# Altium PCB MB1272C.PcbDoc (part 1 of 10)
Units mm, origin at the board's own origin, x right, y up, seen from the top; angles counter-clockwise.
Board outline 101 x 71 mm, 6 copper layers (Top Layer, Signal Layer 1, Signal Layer 2, Signal Layer 3, Signal Layer 4, Bottom Layer), stack 1.552 mm thick; 520 components, 478 nets, 2156 pads, 1894 vias.
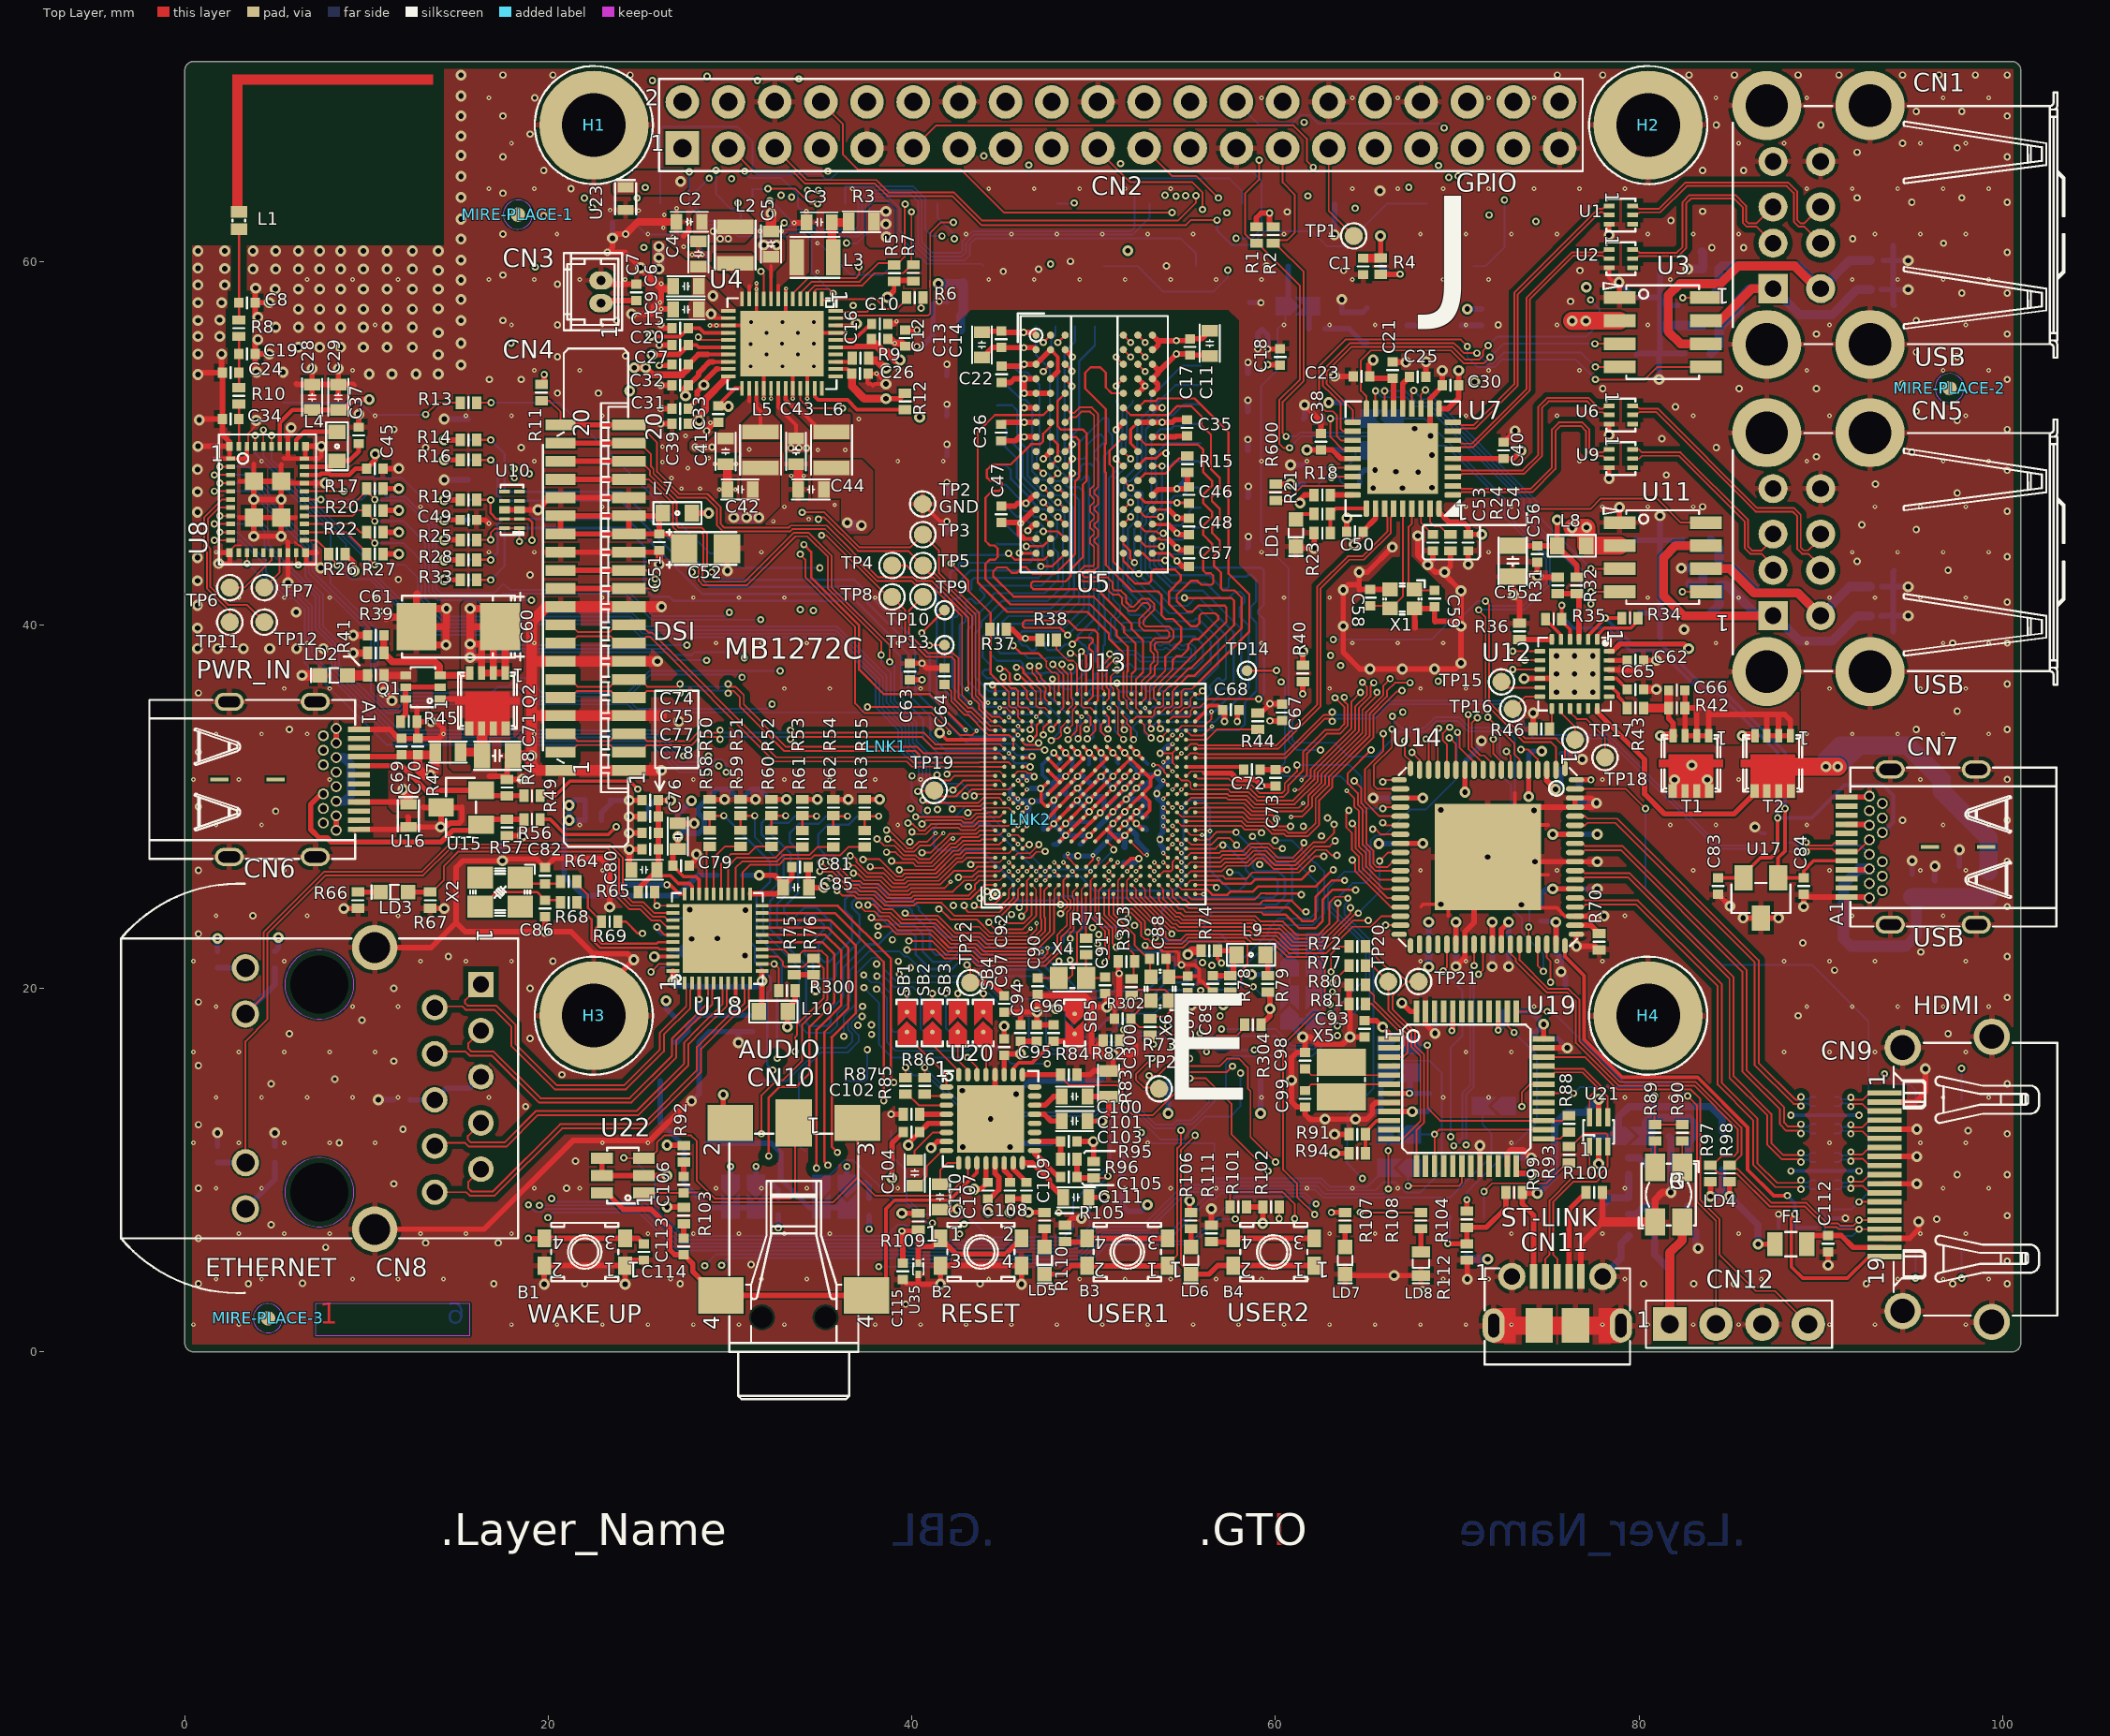
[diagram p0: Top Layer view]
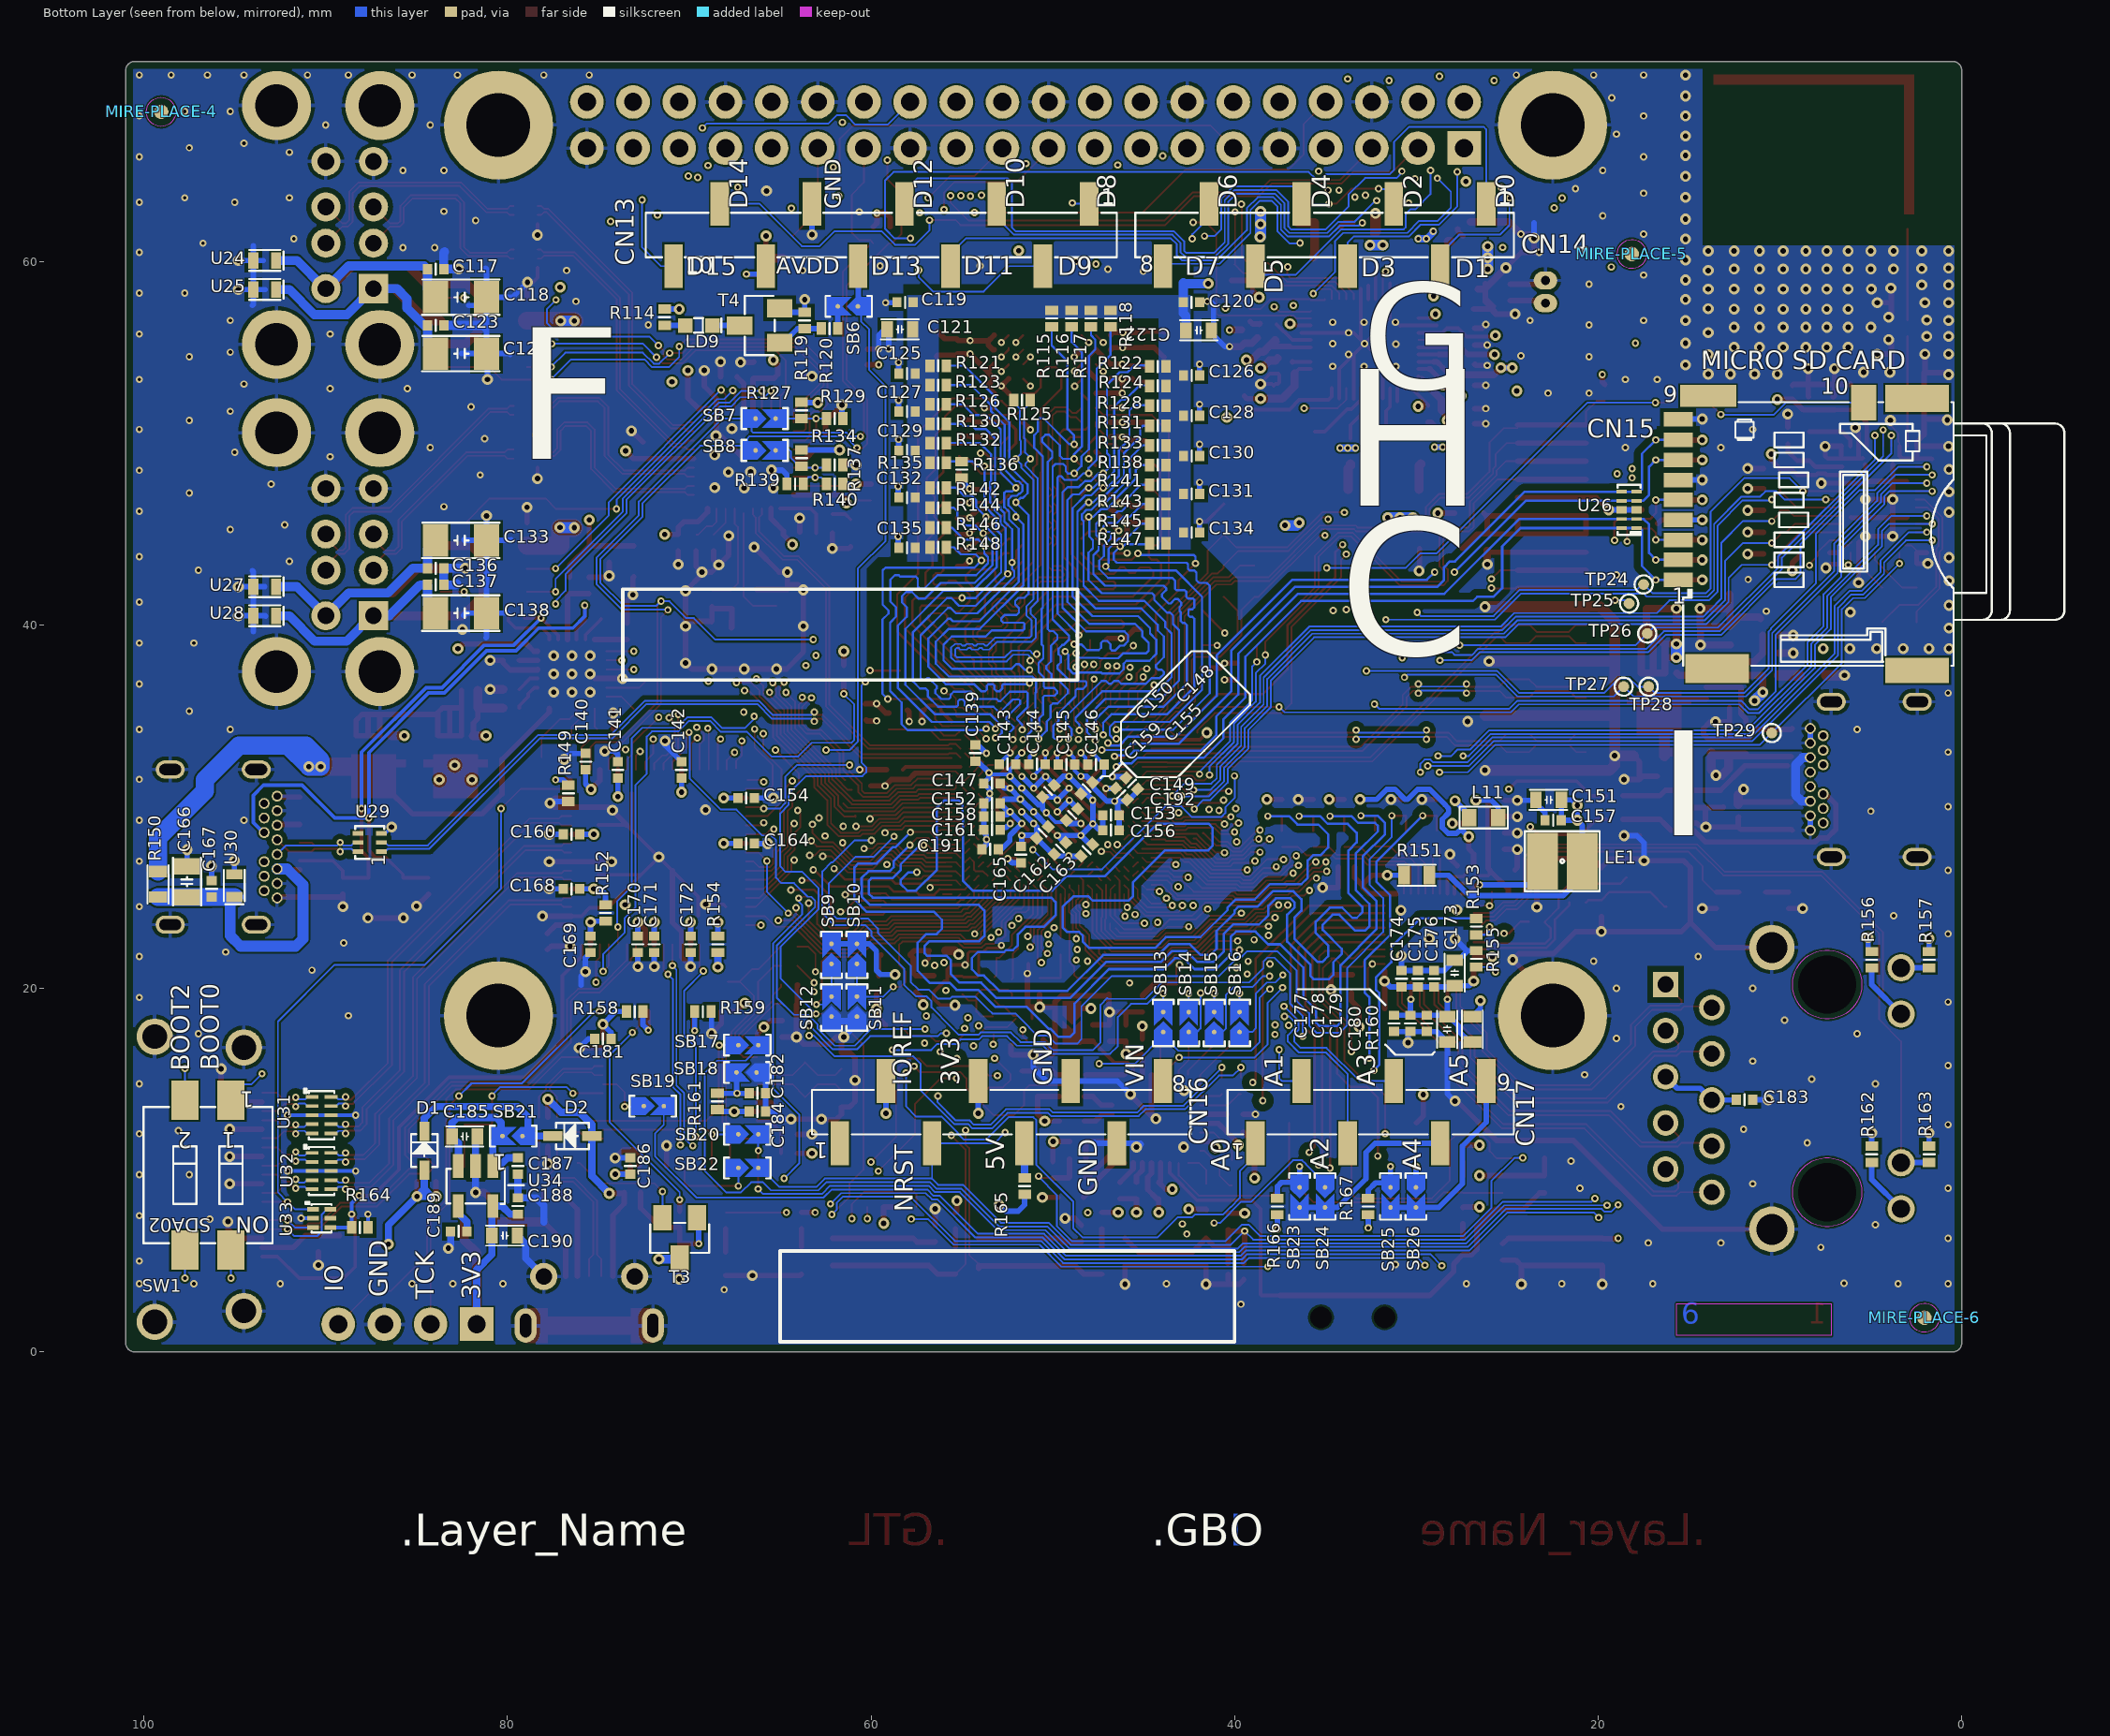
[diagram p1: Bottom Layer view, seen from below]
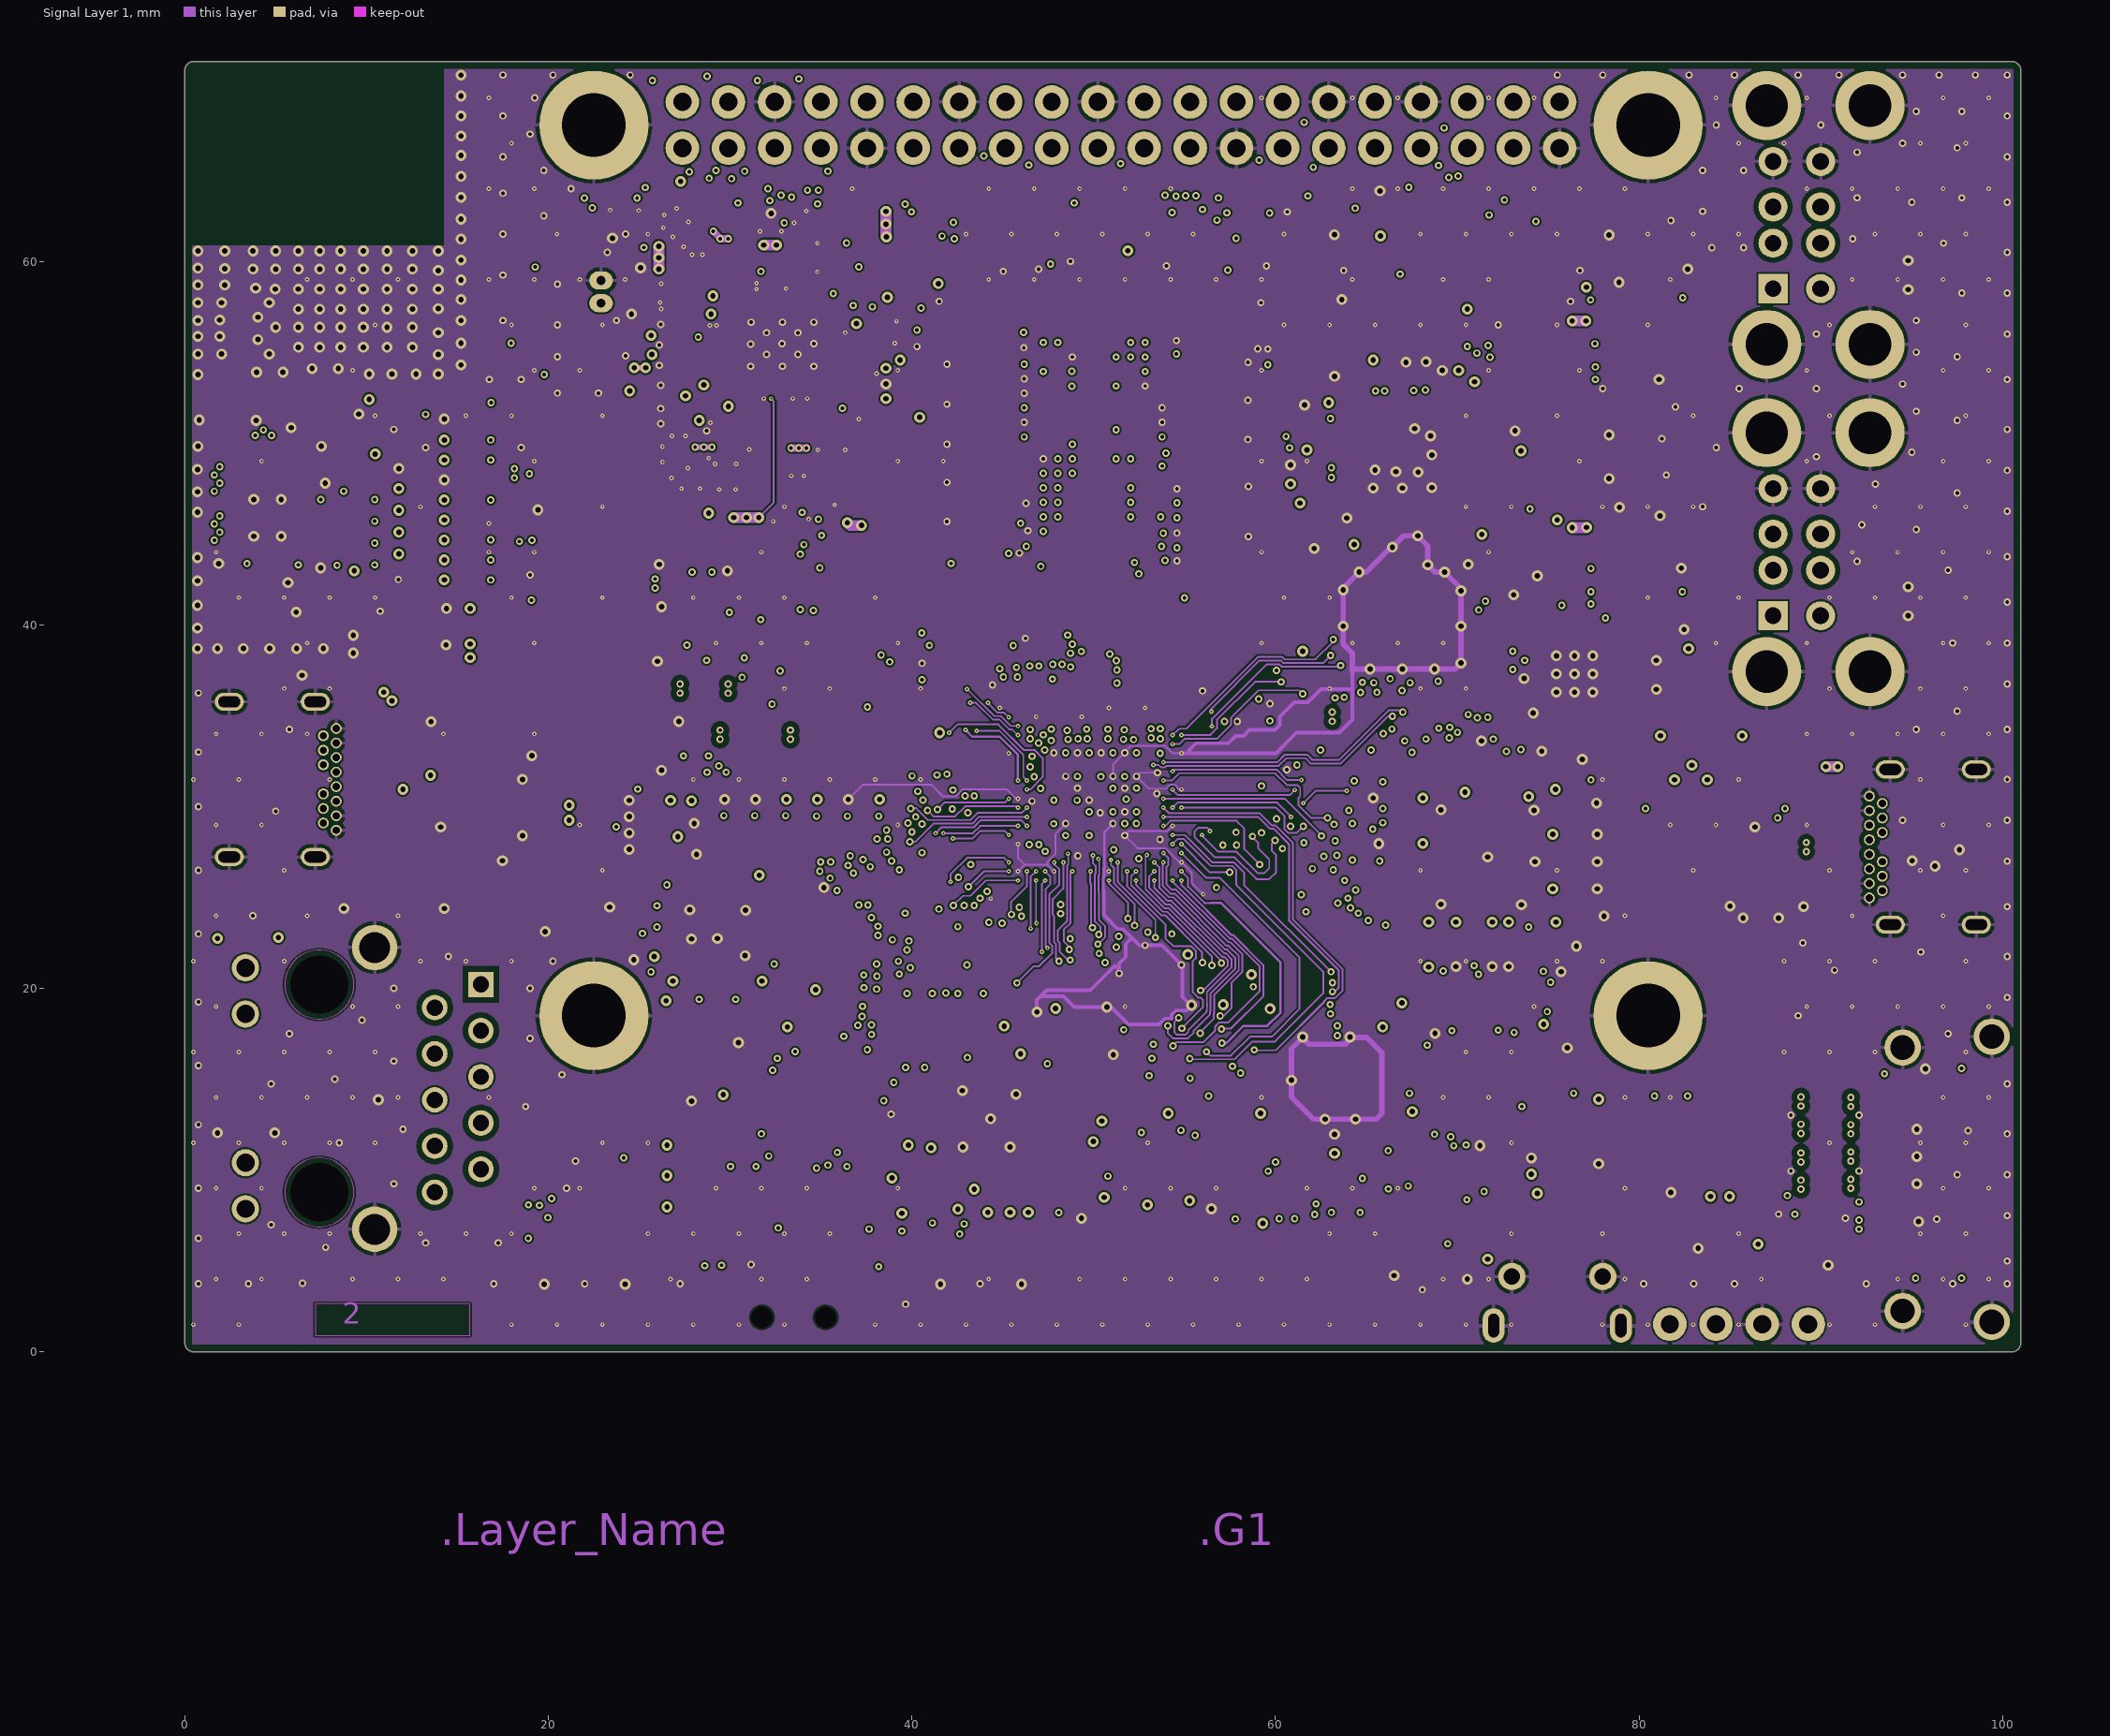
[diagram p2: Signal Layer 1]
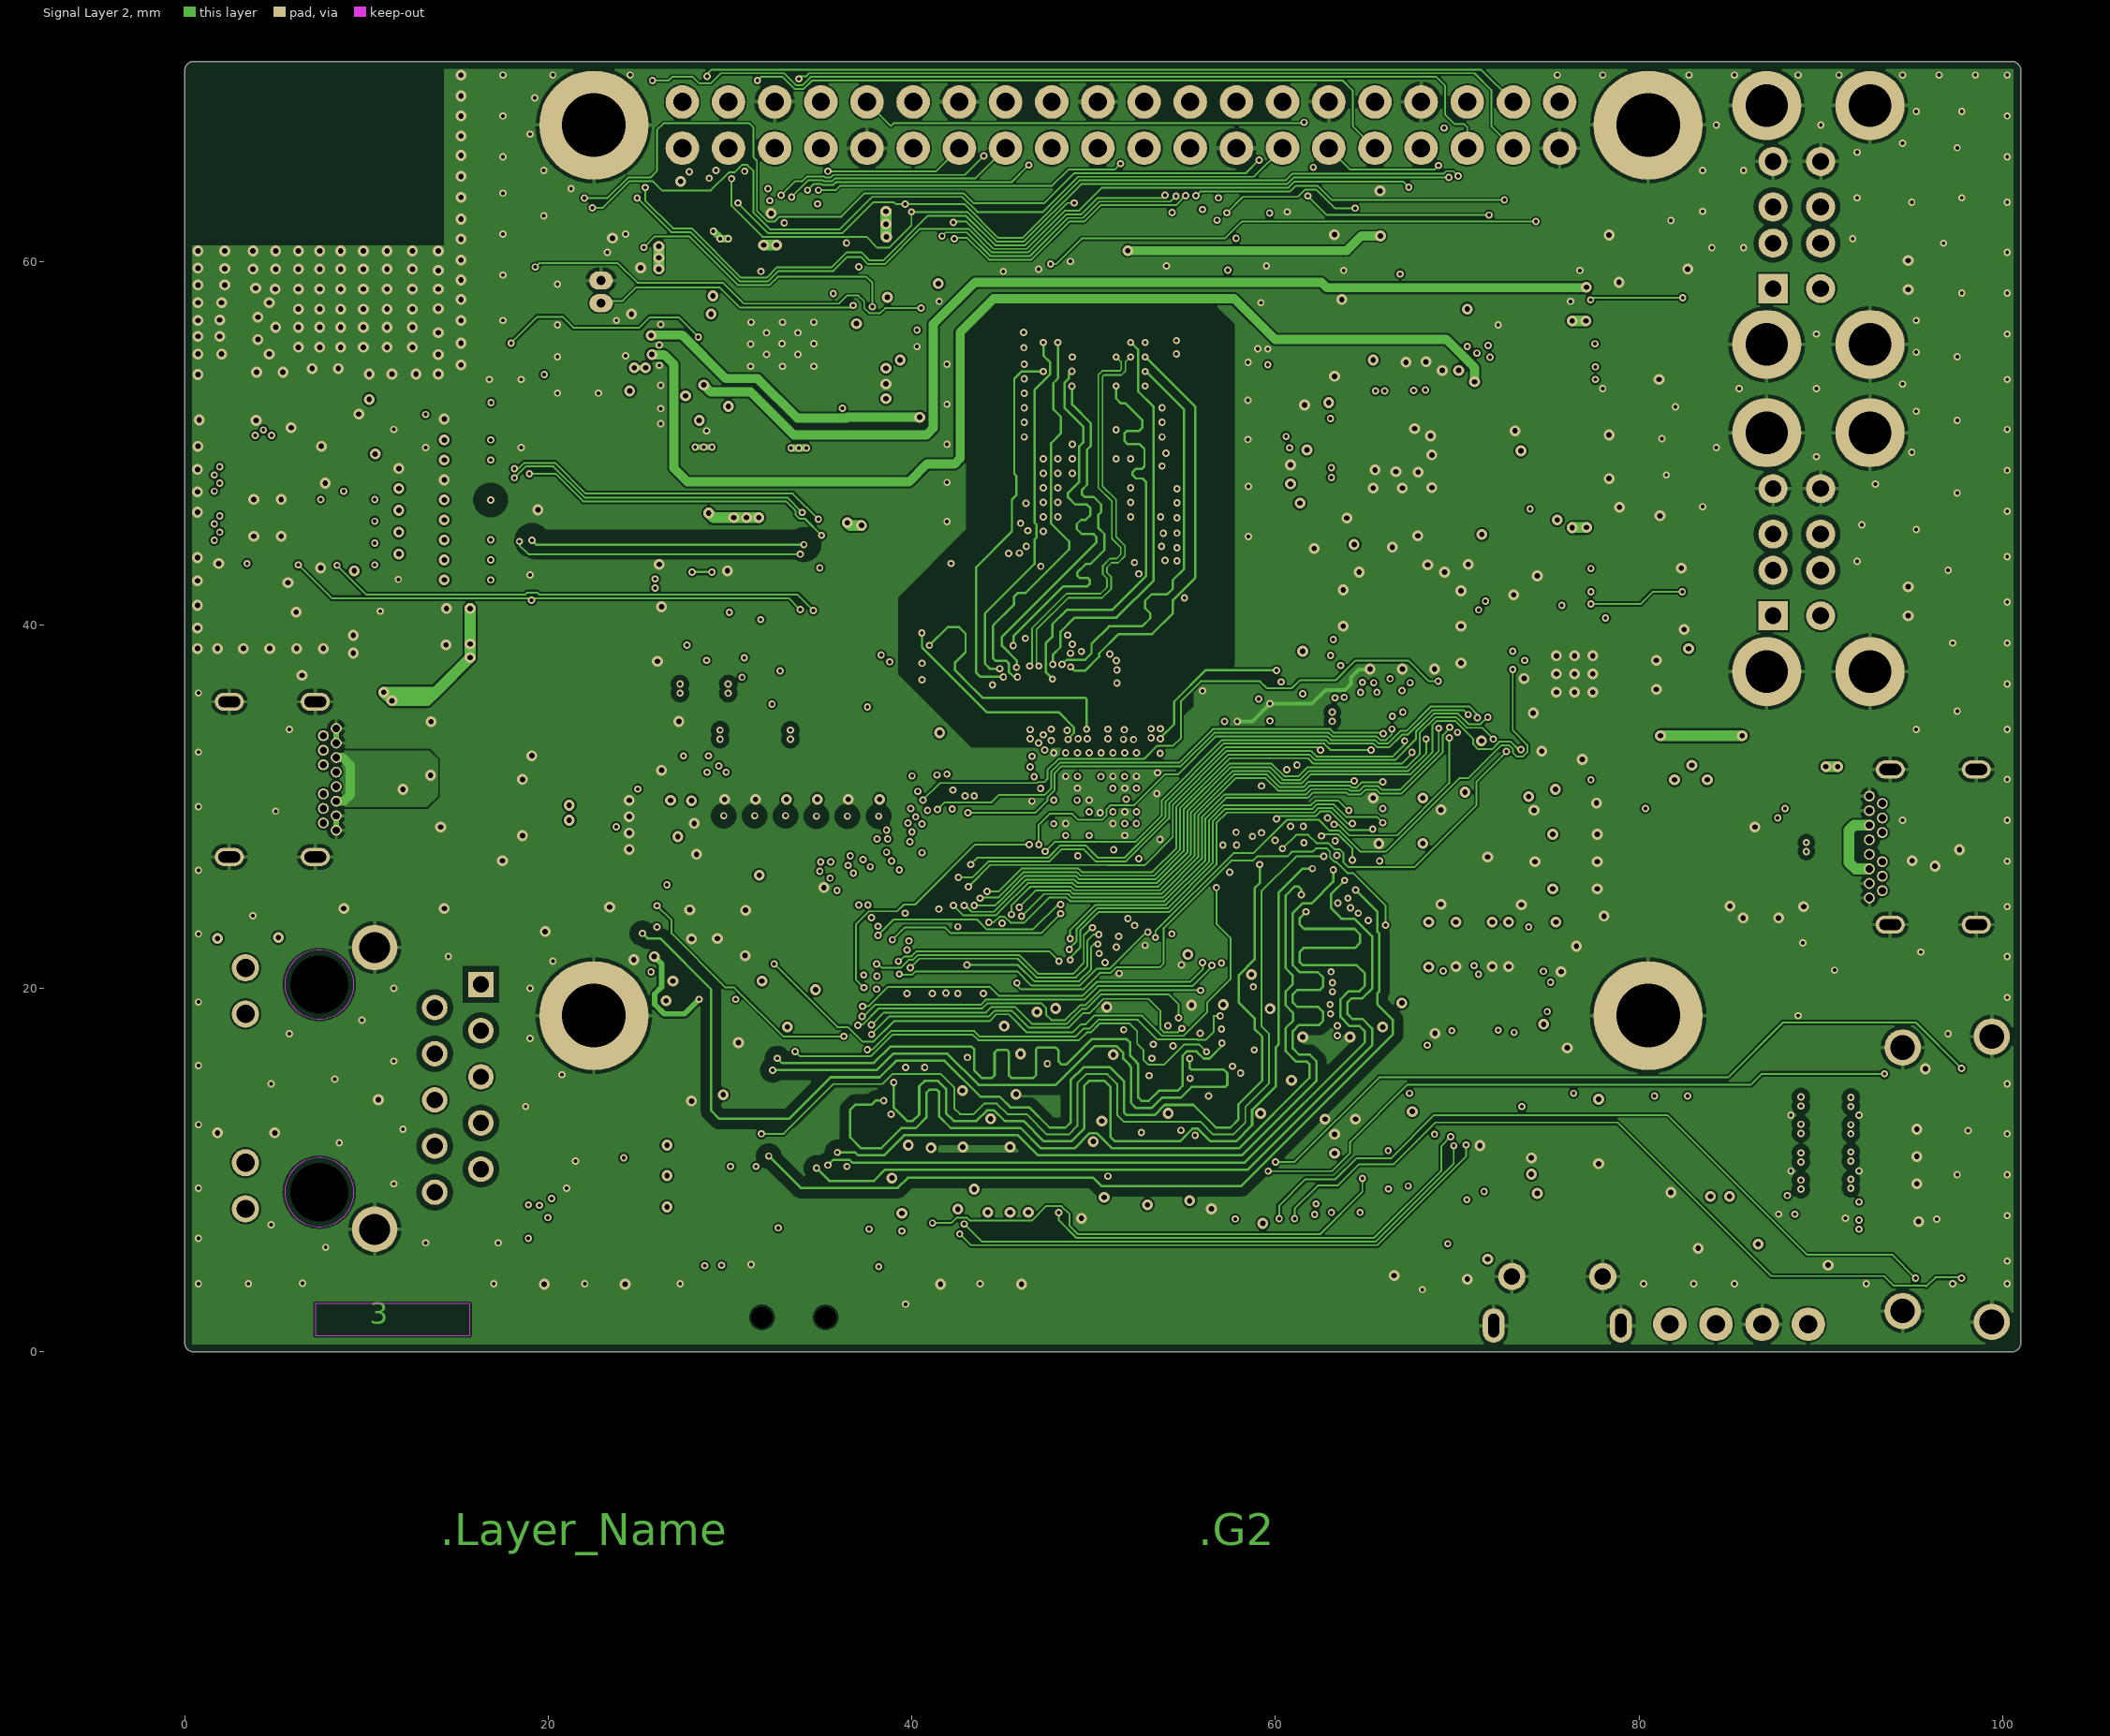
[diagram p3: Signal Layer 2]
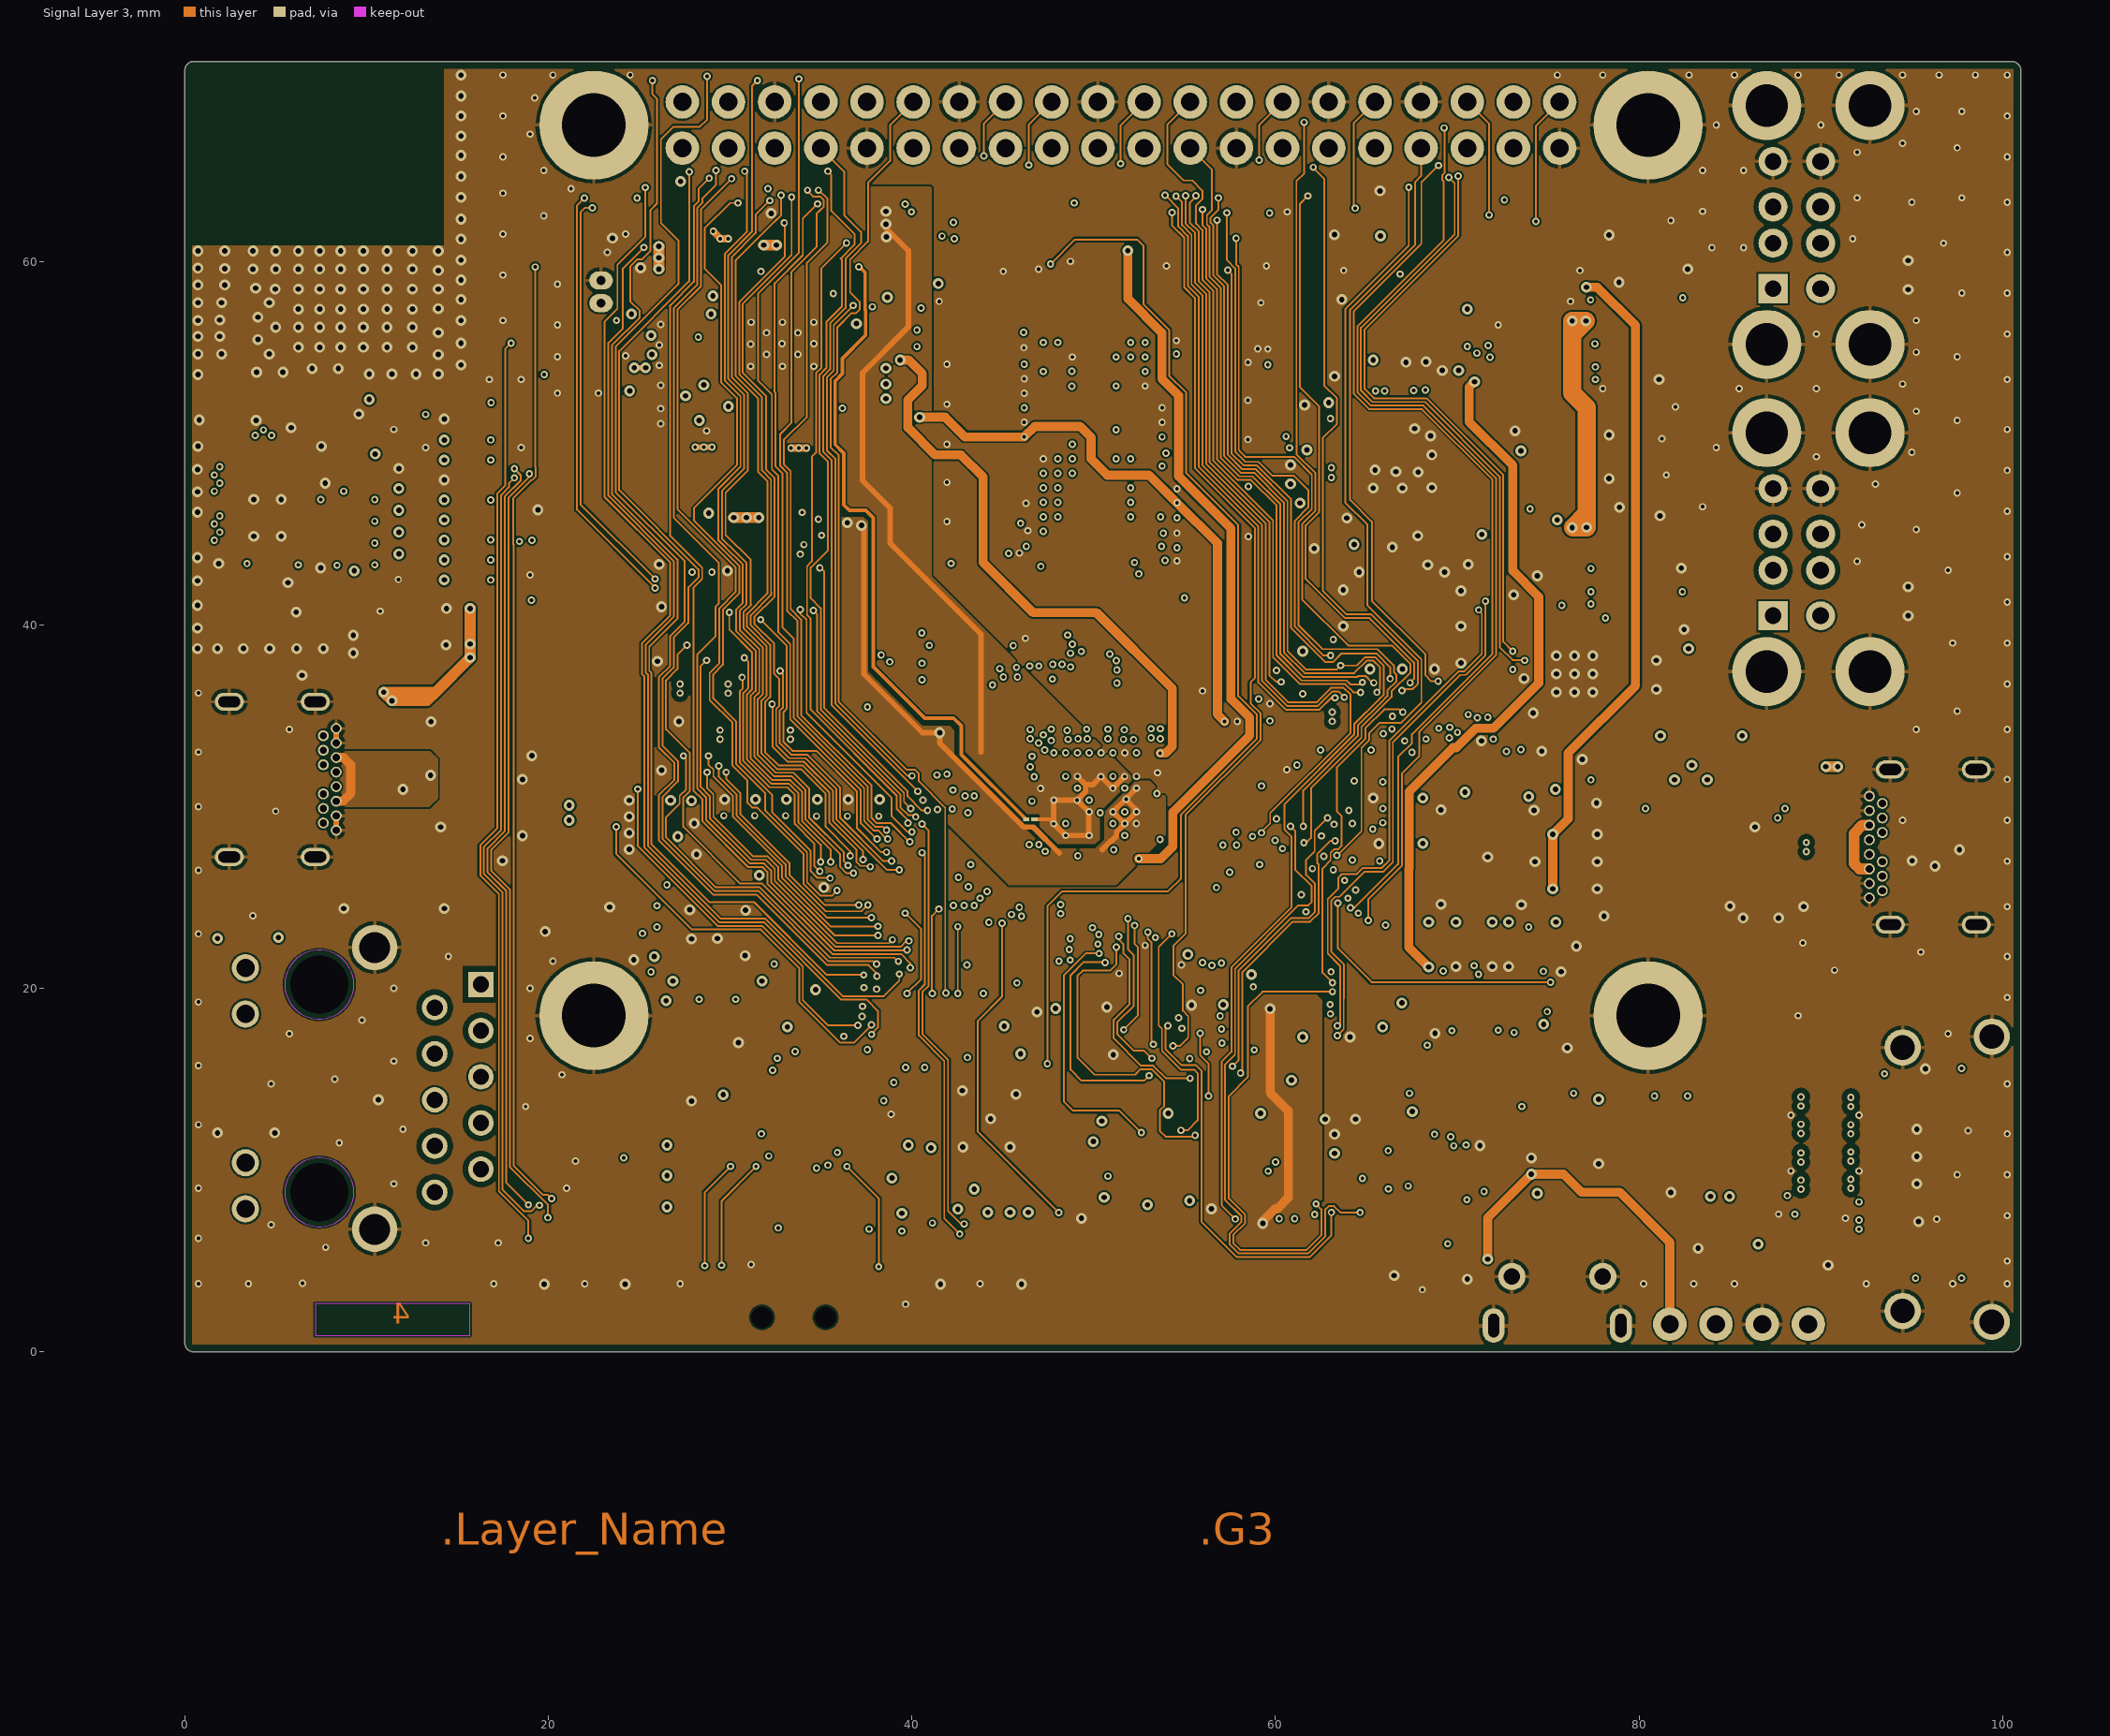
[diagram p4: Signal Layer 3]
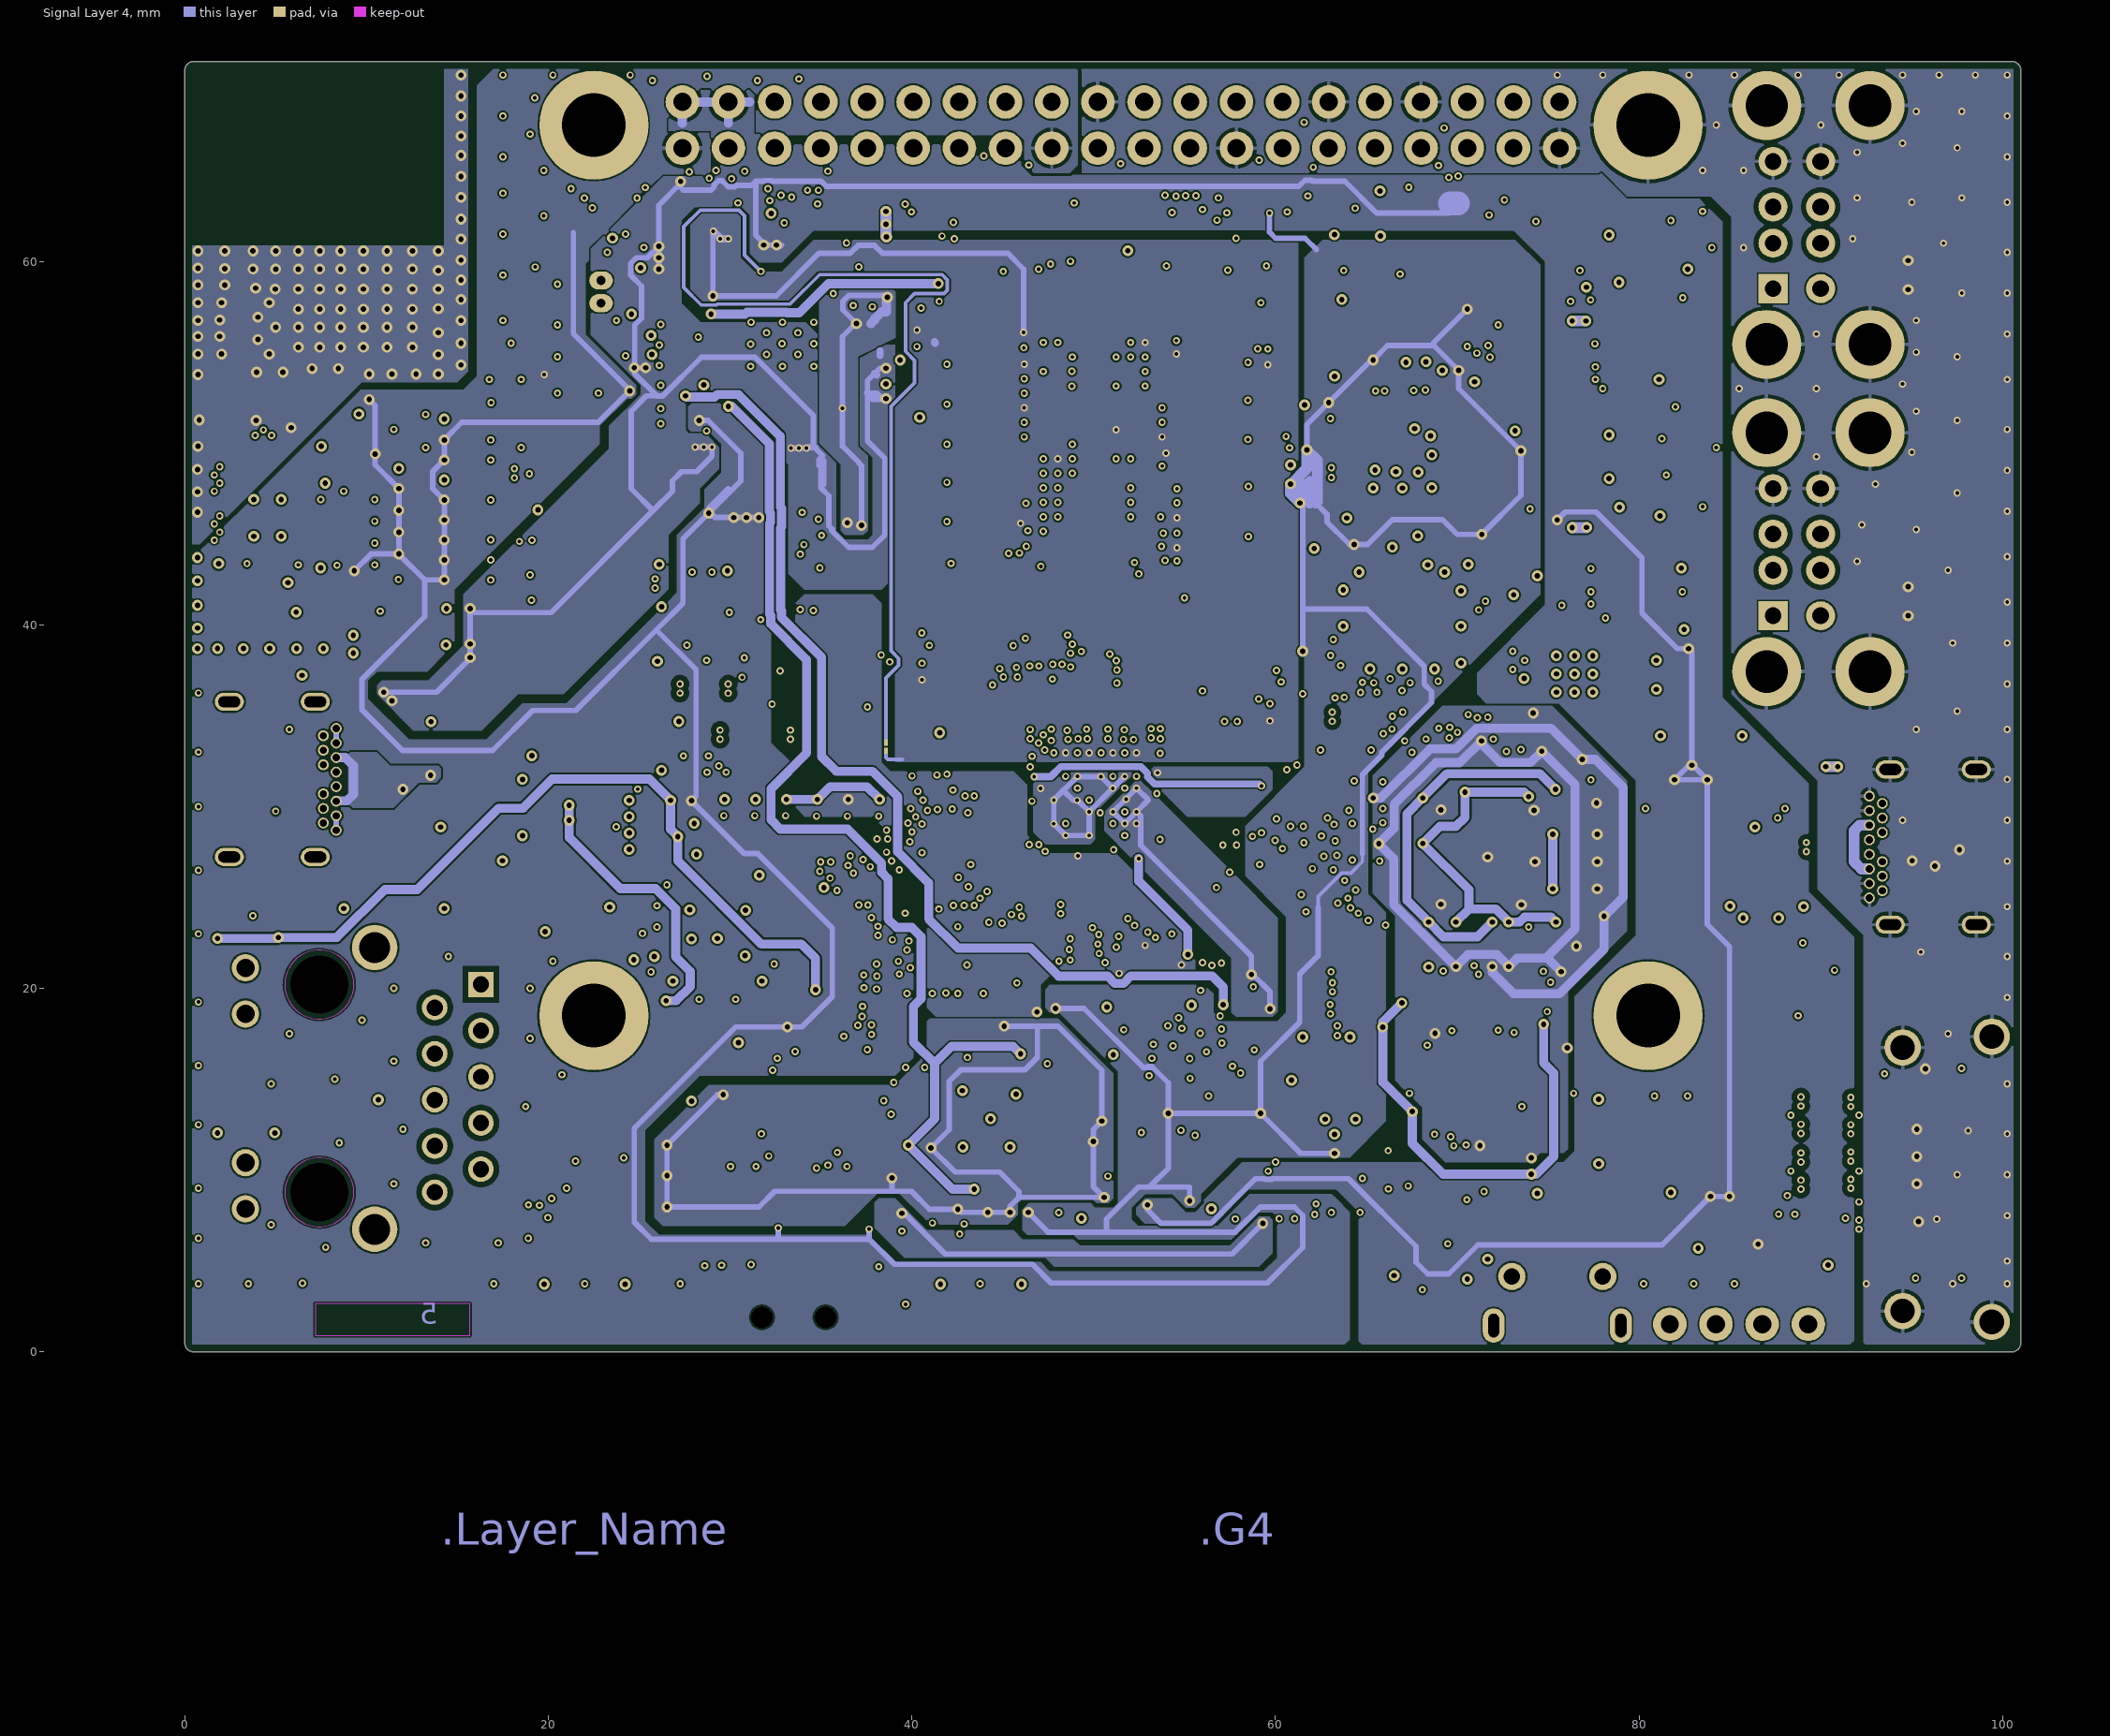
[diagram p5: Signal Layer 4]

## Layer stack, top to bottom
Top Solder: solder mask 0.0203, Solder Resist, Dk 3.5
Top Layer: signal copper 0.035
Dielectric 1: prepreg 0.0986, IT-180A 3313H, Dk 4.2
Signal Layer 1: signal copper 0.035
Dielectric 2: core 0.13, IT-180A, Dk 4.2
Signal Layer 2: signal copper 0.035
Dielectric 3: core 0.885, IT-180A 1080*2, Dk 4.25
Signal Layer 3: signal copper 0.035
Dielectric 4: core 0.13, IT-180A, Dk 4.2
Signal Layer 4: signal copper 0.035
Dielectric 5: prepreg 0.0986, IT-180A 3313H, Dk 4.2
Bottom Layer: signal copper 0.035
Bottom Solder: solder mask 0.0203, Solder Resist, Dk 3.5

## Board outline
0,0.5 ccw(c0.5,0.5) 0.5,0 100.5,0 ccw(c100.5,0.5) 101,0.5 101,70.5 ccw(c100.5,70.5) 100.5,71 0.5,71 ccw(c0.5,70.5) 0,70.5

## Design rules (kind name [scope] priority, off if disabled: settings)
BoardOutlineClearance [All] p1: gap=0.4 ignorepadtopadclearanceinfootprint=FALSE
Clearance Clearance_BGA05 [InComponentClass('CC_BGA05')] p1: gap=0.1 ignorepadtopadclearanceinfootprint=TRUE except(0.09: Arc-Track Track-SMDPad; 0.15: Arc-Fill Track-Fill SMDPad-Fill THPad-Fill Via-Fill Fill-Fill; 0.2: Arc-THPad Track-THPad SMDPad-SMDPad SMDPad-THPad THPad-THPad)
Clearance Clearance_BUS_50R_RGMII_ETH_L1 [InNetClass('NC_BUS_50R_RGMII_ETH-ALL') vs OnLayer('Top Layer')] p2: gap=0.1 ignorepadtopadclearanceinfootprint=TRUE except(0.15: Arc-Fill Track-Fill SMDPad-Fill THPad-Fill Via-Fill Fill-Fill; 0.2: Arc-THPad Track-THPad SMDPad-SMDPad SMDPad-THPad THPad-THPad; 0.26: Track-Track; 0.39: Arc-Poly Track-Poly SMDPad-Poly THPad-Poly Via-Poly Fill-Poly Poly-Poly)
Clearance Clearance_BUS_50R_RGMII_ETH_L6 [InNetClass('NC_BUS_50R_RGMII_ETH-ALL') vs OnLayer('Bottom Layer')] p3: gap=0.1 ignorepadtopadclearanceinfootprint=TRUE except(0.15: Arc-Fill Track-Fill SMDPad-Fill THPad-Fill Via-Fill Fill-Fill; 0.2: Arc-THPad Track-THPad SMDPad-SMDPad SMDPad-THPad THPad-THPad; 0.26: Track-Track; 0.39: Arc-Poly Track-Poly SMDPad-Poly THPad-Poly Via-Poly Fill-Poly Poly-Poly)
Clearance Clearance_BUS_50R_RGMII_ETH_L3 [InNetClass('NC_BUS_50R_RGMII_ETH-ALL') vs OnLayer('Signal Layer 2')] p4: gap=0.1 ignorepadtopadclearanceinfootprint=TRUE except(0.15: Arc-Fill Track-Fill SMDPad-Fill THPad-Fill Via-Fill Fill-Fill; 0.2: Arc-THPad Track-THPad SMDPad-SMDPad SMDPad-THPad THPad-THPad; 0.26: Track-Track; 0.5: Arc-Poly Track-Poly SMDPad-Poly THPad-Poly Via-Poly Fill-Poly Poly-Poly)
Clearance Clearance_DIFFPAIR_100R_DSI [InNetClass('NC_DIFFPAIR_100R_DSI')] p5: gap=0.1 ignorepadtopadclearanceinfootprint=TRUE except(0.15: Arc-Fill Track-Fill SMDPad-Fill THPad-Fill Via-Fill Fill-Fill; 0.2: Arc-THPad Track-THPad SMDPad-SMDPad SMDPad-THPad THPad-THPad; 0.3: Arc-Poly Track-Poly SMDPad-Poly THPad-Poly Via-Poly Fill-Poly Poly-Poly)
Clearance Clearance_DIFFPAIR_100R_RGMII-RJ45 [InNetClass('NC_DIFFPAIR_100R_RGMII-RJ45')] p6: gap=0.1 ignorepadtopadclearanceinfootprint=TRUE except(0.15: Arc-Fill Track-Fill SMDPad-Fill THPad-Fill Via-Fill Fill-Fill; 0.2: Arc-THPad Track-THPad SMDPad-SMDPad SMDPad-THPad THPad-THPad; 0.3: Arc-Poly Track-Poly SMDPad-Poly THPad-Poly Via-Poly Fill-Poly Poly-Poly)
Clearance Clearance_DIFFPAIR_100R_HDMI-TX [InNetClass('NC_DIFFPAIR_100R_HDMI-TX')] p7: gap=0.1 ignorepadtopadclearanceinfootprint=TRUE except(0.15: Arc-Fill Track-Fill SMDPad-Fill THPad-Fill Via-Fill Fill-Fill; 0.2: Arc-THPad Track-THPad SMDPad-SMDPad SMDPad-THPad THPad-THPad; 0.3: Arc-Poly Track-Poly SMDPad-Poly THPad-Poly Via-Poly Fill-Poly Poly-Poly)
Clearance Clearance_DIFFPAIR_90R_USB [InNetClass('NC_DIFFPAIR_90R_USB')] p8: gap=0.1 ignorepadtopadclearanceinfootprint=TRUE except(0.09: Track-Track; 0.15: Arc-Fill Track-Fill SMDPad-Fill THPad-Fill Via-Fill Fill-Fill; 0.2: Arc-THPad Track-THPad SMDPad-SMDPad SMDPad-THPad THPad-THPad; 0.27: Arc-Poly Track-Poly SMDPad-Poly THPad-Poly Via-Poly Fill-Poly Poly-Poly)
Clearance Clearance_BUS_50R_SDMMC1 [InNetClass('NC_BUS_50R_SDMMC1') vs OnLayer('Bottom Layer')] p9: gap=0.1 ignorepadtopadclearanceinfootprint=TRUE except(0.15: Arc-Fill Track-Fill SMDPad-Fill THPad-Fill Via-Fill Fill-Fill; 0.2: Arc-THPad Track-THPad SMDPad-SMDPad SMDPad-THPad THPad-THPad; 0.26: Track-Track; 0.39: Arc-Poly Track-Poly SMDPad-Poly THPad-Poly Via-Poly Fill-Poly Poly-Poly)
Clearance Clearance_ANTENNA_50R_WIFI [InNetClass('NC_ANTENNA_50R_WIFI')] p10: gap=0.1 ignorepadtopadclearanceinfootprint=TRUE except(0.15: Arc-Fill Track-Fill SMDPad-Fill THPad-Fill Via-Fill Fill-Fill; 0.2: Arc-THPad Track-Track Track-SMDPad Track-THPad SMDPad-SMDPad SMDPad-THPad THPad-THPad; 0.39: Arc-Poly Track-Poly SMDPad-Poly THPad-Poly Via-Poly Fill-Poly Poly-Poly)
Clearance Clearance_BUS_50R_SDMMC1_CK [InNetClass('NC_BUS_50R_SDMMC1_CK') vs OnLayer('Signal Layer 2')] p11: gap=0.1 ignorepadtopadclearanceinfootprint=TRUE except(0.15: Arc-Fill Track-Fill SMDPad-Fill THPad-Fill Via-Fill Fill-Fill; 0.2: Arc-THPad Track-THPad SMDPad-SMDPad SMDPad-THPad THPad-THPad; 0.26: Track-Track; 0.75: Arc-Poly Track-Poly SMDPad-Poly THPad-Poly Via-Poly Fill-Poly Poly-Poly)
Clearance [All] p12: gap=0.1 ignorepadtopadclearanceinfootprint=TRUE except(0.08: Track-SMDPad; 0.15: Arc-Fill Track-Fill SMDPad-Fill THPad-Fill Via-Fill Fill-Fill; 0.2: Arc-THPad Track-THPad SMDPad-SMDPad SMDPad-THPad THPad-THPad)
ComponentClearance [All] p1 off: gap=0.025 collisioncheckmode=3 verticalgap=2540 showdistances=TRUE
DiffPairsRouting DiffPairsRouting_90R_USB [InDifferentialPairClass('DIFFPAIR_90R_USB')] p1: maxlimit=0.09 minlimit=0.09 mostfreqgap=0.09 toplayer_minwidth=0.09 toplayer_maxwidth=0.1 toplayer_prefwidth=0.1 midlayer1_minwidth=0.09 midlayer1_maxwidth=0.1 midlayer1_prefwidth=0.1 midlayer2_minwidth=0.09 midlayer2_maxwidth=0.1 midlayer2_prefwidth=0.1 midlayer3_minwidth=0.09 midlayer3_maxwidth=0.1 midlayer3_prefwidth=0.1 midlayer4_minwidth=0.09 midlayer4_maxwidth=0.1 midlayer4_prefwidth=0.1 bottomlayer_minwidth=0.09 bottomlayer_maxwidth=0.1 bottomlayer_prefwidth=0.1 maxuncoupledlength=12.7
DiffPairsRouting DiffPairsRouting_100R_DDR [InDifferentialPairClass('DIFFPAIR_100R_DDR')] p2: maxlimit=0.14 minlimit=0.13 mostfreqgap=0.14 toplayer_maxgap=0.13 toplayer_prefgap=0.13 toplayer_minwidth=0.09 toplayer_maxwidth=0.1 toplayer_prefwidth=0.1 midlayer1_maxgap=0.13 midlayer1_prefgap=0.13 midlayer1_minwidth=0.09 midlayer1_maxwidth=0.1 midlayer1_prefwidth=0.1 midlayer2_mingap=0.14 midlayer2_minwidth=0.09 midlayer2_maxwidth=0.09 midlayer2_prefwidth=0.09 midlayer3_maxgap=0.13 midlayer3_prefgap=0.13 midlayer3_minwidth=0.09 midlayer3_maxwidth=0.1 midlayer3_prefwidth=0.1 midlayer4_maxgap=0.13 midlayer4_prefgap=0.13 midlayer4_minwidth=0.09 midlayer4_maxwidth=0.1 midlayer4_prefwidth=0.1 bottomlayer_maxgap=0.13 bottomlayer_prefgap=0.13 bottomlayer_minwidth=0.09 bottomlayer_maxwidth=0.1 bottomlayer_prefwidth=0.1 maxuncoupledlength=12.7
DiffPairsRouting DiffPairsRouting_100R_HDMI-TX [InDifferentialPairClass('DIFFPAIR_100R_HDMI-TX')] p3: maxlimit=0.13 minlimit=0.13 mostfreqgap=0.13 toplayer_minwidth=0.09 toplayer_maxwidth=0.1 toplayer_prefwidth=0.1 midlayer1_minwidth=0.09 midlayer1_maxwidth=0.1 midlayer1_prefwidth=0.1 midlayer2_minwidth=0.09 midlayer2_maxwidth=0.1 midlayer2_prefwidth=0.1 midlayer3_minwidth=0.09 midlayer3_maxwidth=0.1 midlayer3_prefwidth=0.1 midlayer4_minwidth=0.09 midlayer4_maxwidth=0.1 midlayer4_prefwidth=0.1 bottomlayer_minwidth=0.09 bottomlayer_maxwidth=0.1 bottomlayer_prefwidth=0.1 maxuncoupledlength=12.7
DiffPairsRouting DiffPairsRouting_100R_DSI [InDifferentialPairClass('DIFFPAIR_100R_DSI')] p4: maxlimit=0.13 minlimit=0.13 mostfreqgap=0.13 toplayer_minwidth=0.09 toplayer_maxwidth=0.1 toplayer_prefwidth=0.1 midlayer1_minwidth=0.09 midlayer1_maxwidth=0.1 midlayer1_prefwidth=0.1 midlayer2_minwidth=0.09 midlayer2_maxwidth=0.1 midlayer2_prefwidth=0.1 midlayer3_minwidth=0.09 midlayer3_maxwidth=0.1 midlayer3_prefwidth=0.1 midlayer4_minwidth=0.09 midlayer4_maxwidth=0.1 midlayer4_prefwidth=0.1 bottomlayer_minwidth=0.09 bottomlayer_maxwidth=0.1 bottomlayer_prefwidth=0.1 maxuncoupledlength=12.7
DiffPairsRouting DiffPairsRouting_100R_RGMII-RJ45 [InDifferentialPairClass('DIFFPAIR_100R_RGMII-RJ45')] p5: maxlimit=0.13 minlimit=0.13 mostfreqgap=0.13 toplayer_minwidth=0.09 toplayer_maxwidth=0.1 toplayer_prefwidth=0.1 midlayer1_minwidth=0.09 midlayer1_maxwidth=0.1 midlayer1_prefwidth=0.1 midlayer2_minwidth=0.09 midlayer2_maxwidth=0.1 midlayer2_prefwidth=0.1 midlayer3_minwidth=0.09 midlayer3_maxwidth=0.1 midlayer3_prefwidth=0.1 midlayer4_minwidth=0.09 midlayer4_maxwidth=0.1 midlayer4_prefwidth=0.1 bottomlayer_minwidth=0.09 bottomlayer_maxwidth=0.1 bottomlayer_prefwidth=0.1 maxuncoupledlength=12.7
FanoutControl Fanout_BGA [IsBGA] p1: bgadir=Out bgaviamode=Closest fanoutstyle=Auto fanoutdirection=Alternating viagrid=0.025 // Fanout_BGA (Default Rule)
FanoutControl Fanout_LCC [IsLCC] p2: bgadir=Out bgaviamode=Closest fanoutstyle=Auto fanoutdirection=Alternating viagrid=0.025 // Fanout_LCC (Default Rule)
FanoutControl Fanout_SOIC [IsSOIC] p3: bgadir=Out bgaviamode=Closest fanoutstyle=Auto fanoutdirection=Alternating viagrid=0.025 // Fanout_SOIC (Default Rule)
FanoutControl Fanout_Small [(CompPinCount < 5)] p4: bgadir=Out bgaviamode=Closest fanoutstyle=Auto fanoutdirection=OutThenIn viagrid=0.025 // Fanout_Small (Default Rule)
FanoutControl Fanout_Default [All] p5: bgadir=Out bgaviamode=Closest fanoutstyle=Auto fanoutdirection=Alternating viagrid=0.025 // Fanout_Default (Default Rule)
Height [All] p1 off: minheight=0 maxheight=100 prefheight=0.5
HoleSize [All] p1: absolutevalues=TRUE maxlimit=10 minlimit=0.15 maxpercent=80.000 minpercent=20.000
HoleToHoleClearance [All] p1: gap=0.25 allowstackedmicrovias=TRUE
Length Length_BUS_50R_SDMMC1_ALL [InNetClass('NC_BUS_50R_SDMMC1_ALL')] p1: maxlimit=100 minlimit=0
MatchedLengths MatchedLengths_BUS_50R_RGMII_ETH-ALL [InNetClass('NC_BUS_50R_RGMII_ETH-ALL')] p1: tolerance=10 checknetsindiffpair=FALSE checkdiffpairvsdiffpair=TRUE checkxsignals=TRUE checkothers=TRUE
MatchedLengths MatchedLengths_BUS_50R_SDMMC1_ALL [InNetClass('NC_BUS_50R_SDMMC1_ALL')] p2: tolerance=5 checknetsindiffpair=FALSE checkdiffpairvsdiffpair=TRUE checkxsignals=TRUE checkothers=TRUE
MatchedLengths MatchedLengths_DIFFPAIR_100R_DSI [InDifferentialPairClass('DIFFPAIR_100R_DSI')] p3: tolerance=5 checknetsindiffpair=FALSE checkdiffpairvsdiffpair=TRUE checkxsignals=TRUE checkothers=TRUE
MatchedLengths MatchedLengths_DIFFPAIR_100R_HDMI-TX_1-2 [InDifferentialPairClass('DIFFPAIR_100R_HDMI-TX_LENGTH_1-2')] p4: tolerance=4 checknetsindiffpair=FALSE checkdiffpairvsdiffpair=TRUE checkxsignals=TRUE checkothers=TRUE
MatchedLengths MatchedLengths_DIFFPAIR_100R_HDMI-TX_2-2 [InDifferentialPairClass('DIFFPAIR_100R_HDMI-TX_LENGTH_2-2')] p5: tolerance=4 checknetsindiffpair=FALSE checkdiffpairvsdiffpair=TRUE checkxsignals=TRUE checkothers=TRUE
MatchedLengths MatchedLengths_DIFFPAIR_90R_USB [InDifferentialPairClass('DIFFPAIR_90R_USB_LENGTH')] p6: tolerance=5 checknetsindiffpair=FALSE checkdiffpairvsdiffpair=TRUE checkxsignals=TRUE checkothers=TRUE
MinimumSolderMaskSliver [All] p1: minsoldermaskwidth=0
PlaneClearance [All] p1: clearance=0.6
PolygonConnect PolygonConnect_14 [All vs IsNamedPolygon('NO TR')] p1: thpad.connectstyle=Relief thpad.reliefconductorwidth=0.254 thpad.reliefentries=4 thpad.polygonreliefangle="90 Angle" thpad.airgapwidth=0.254 smdpad.connectstyle=Direct smdpad.reliefconductorwidth=0.254 smdpad.reliefentries=4 smdpad.polygonreliefangle="90 Angle" smdpad.airgapwidth=0.254 via.connectstyle=Direct via.reliefconductorwidth=0.254 via.reliefentries=4 via.polygonreliefangle="90 Angle" via.airgapwidth=0.254
PolygonConnect PolygonConnect_13 [All vs IsNamedPolygon('NETC66_2_L01_P093')] p2: connectstyle=Direct reliefconductorwidth=0.254 reliefentries=4 polygonreliefangle="90 Angle" airgapwidth=0.254
PolygonConnect PolygonConnect_12 [All vs IsNamedPolygon('NETC69_2_L01_P091')] p3: connectstyle=Direct reliefconductorwidth=0.254 reliefentries=4 polygonreliefangle="90 Angle" airgapwidth=0.254
PolygonConnect PolygonConnect_11 [All vs IsNamedPolygon('NETC71_2_L01_P088')] p4: connectstyle=Direct reliefconductorwidth=0.254 reliefentries=4 polygonreliefangle="90 Angle" airgapwidth=0.254
PolygonConnect PolygonConnect_10 [All vs IsNamedPolygon('5V_VIN_L01_P096')] p5: connectstyle=Direct reliefconductorwidth=0.254 reliefentries=4 polygonreliefangle="90 Angle" airgapwidth=0.254
PolygonConnect PolygonConnect_9 [All vs IsNamedPolygon('NETC195_2_L01_P093')] p6: connectstyle=Direct reliefconductorwidth=0.254 reliefentries=4 polygonreliefangle="90 Angle" airgapwidth=0.254
PolygonConnect PolygonConnect_8 [All vs IsNamedPolygon('5V_VIN_L01_P095')] p7: connectstyle=Direct reliefconductorwidth=0.254 reliefentries=4 polygonreliefangle="90 Angle" airgapwidth=0.254
PolygonConnect PolygonConnect_7 [All vs IsNamedPolygon('5V_VIN_L01_P020')] p8: connectstyle=Direct reliefconductorwidth=0.254 reliefentries=4 polygonreliefangle="90 Angle" airgapwidth=0.254
PolygonConnect PolygonConnect_6 [All vs IsNamedPolygon('NETC42_2_L01_P091')] p9: connectstyle=Direct reliefconductorwidth=0.254 reliefentries=4 polygonreliefangle="90 Angle" airgapwidth=0.254
PolygonConnect PolygonConnect_5 [All vs IsNamedPolygon('NETC44_2_L01_P088')] p10: connectstyle=Direct reliefconductorwidth=0.254 reliefentries=4 polygonreliefangle="90 Angle" airgapwidth=0.254
PolygonConnect PolygonConnect_4 [All vs IsNamedPolygon('NETC42_2_L01_P014')] p11: connectstyle=Direct reliefconductorwidth=0.254 reliefentries=4 polygonreliefangle="90 Angle" airgapwidth=0.254
PolygonConnect PolygonConnect_3 [All vs IsNamedPolygon('NETC42_2_L01_P078')] p12: connectstyle=Direct reliefconductorwidth=0.254 reliefentries=4 polygonreliefangle="90 Angle" airgapwidth=0.254
PolygonConnect PolygonConnect_2 [All vs IsNamedPolygon('GND_L01_P014')] p13: thpad.connectstyle=Relief thpad.reliefconductorwidth=0.3 thpad.reliefentries=4 thpad.polygonreliefangle="90 Angle" thpad.airgapwidth=0.2 smdpad.connectstyle=Relief smdpad.reliefconductorwidth=0.3 smdpad.reliefentries=4 smdpad.polygonreliefangle="90 Angle" smdpad.airgapwidth=0.2 via.connectstyle=Direct via.reliefconductorwidth=0.254 via.reliefentries=4 via.polygonreliefangle="90 Angle" via.airgapwidth=0.254
PolygonConnect PolygonConnect_1 [InNet('VTT_DDR')] p14: connectstyle=Direct reliefconductorwidth=0.254 reliefentries=4 polygonreliefangle="90 Angle" airgapwidth=0.254
PolygonConnect [All] p15: thpad.connectstyle=Relief thpad.reliefconductorwidth=0.2 thpad.reliefentries=4 thpad.polygonreliefangle="90 Angle" thpad.airgapwidth=0.2 smdpad.connectstyle=NoConnect smdpad.reliefconductorwidth=0.254 smdpad.reliefentries=4 smdpad.polygonreliefangle="90 Angle" smdpad.airgapwidth=0.2 via.connectstyle=Direct via.reliefconductorwidth=0.254 via.reliefentries=4 via.polygonreliefangle="90 Angle" via.airgapwidth=0.254
RoutingLayers RoutingLayers_BUS_50R_RGMII_ETH-ALL [InNetClass('NC_BUS_50R_RGMII_ETH-ALL')] p1: top layer_v5=TRUE mid layer 1_v5=TRUE mid layer 2_v5=TRUE mid layer 3_v5=TRUE mid layer 4_v5=TRUE bottom layer_v5=TRUE
RoutingLayers RoutingLayers_BUS_50R_SDMMC1_CK [InNetClass('NC_BUS_50R_SDMMC1_CK')] p2: top layer_v5=TRUE mid layer 1_v5=TRUE mid layer 2_v5=TRUE mid layer 3_v5=TRUE mid layer 4_v5=TRUE bottom layer_v5=TRUE
RoutingLayers RoutingLayers_BUS_50R_SDMMC1 [InNetClass('NC_BUS_50R_SDMMC1')] p3: top layer_v5=TRUE mid layer 1_v5=TRUE mid layer 2_v5=TRUE mid layer 3_v5=TRUE mid layer 4_v5=TRUE bottom layer_v5=TRUE
RoutingLayers RoutingLayers_ANTENNA_50R_WIFI [InNetClass('NC_ANTENNA_50R_WIFI')] p4: top layer_v5=TRUE mid layer 1_v5=TRUE mid layer 2_v5=TRUE mid layer 3_v5=TRUE mid layer 4_v5=TRUE bottom layer_v5=TRUE
RoutingLayers RoutingLayers_SINGLE_55R_DDR [InNetClass('NC_SINGLE_55R_DDR')] p5: top layer_v5=TRUE mid layer 1_v5=TRUE mid layer 2_v5=TRUE mid layer 3_v5=TRUE mid layer 4_v5=TRUE bottom layer_v5=TRUE
RoutingLayers RoutingLayers_DIFFPAIR_100R_DDR [InDifferentialPairClass('DIFFPAIR_100R_DDR')] p6: top layer_v5=TRUE mid layer 1_v5=TRUE mid layer 2_v5=TRUE mid layer 3_v5=TRUE mid layer 4_v5=TRUE bottom layer_v5=TRUE
RoutingLayers RoutingLayers_DIFFPAIR_100R_DSI [InDifferentialPairClass('DIFFPAIR_100R_DSI')] p7: top layer_v5=TRUE mid layer 1_v5=TRUE mid layer 2_v5=TRUE mid layer 3_v5=TRUE mid layer 4_v5=TRUE bottom layer_v5=TRUE
RoutingLayers RoutingLayers_DIFFPAIR_100R_RGMII-RJ45 [InDifferentialPairClass('DIFFPAIR_100R_RGMII-RJ45')] p8: top layer_v5=TRUE mid layer 1_v5=TRUE mid layer 2_v5=TRUE mid layer 3_v5=TRUE mid layer 4_v5=TRUE bottom layer_v5=TRUE
RoutingLayers RoutingLayers_DIFFPAIR_100R_HDMI-TX [InDifferentialPairClass('DIFFPAIR_100R_HDMI-TX')] p9: top layer_v5=TRUE mid layer 1_v5=TRUE mid layer 2_v5=TRUE mid layer 3_v5=TRUE mid layer 4_v5=TRUE bottom layer_v5=TRUE
RoutingLayers RoutingLayers_DIFFPAIR_90R_USB [InDifferentialPairClass('DIFFPAIR_90R_USB')] p10: top layer_v5=TRUE mid layer 1_v5=TRUE mid layer 2_v5=TRUE mid layer 3_v5=TRUE mid layer 4_v5=TRUE bottom layer_v5=TRUE
RoutingLayers [All] p11: top layer_v5=TRUE mid layer 1_v5=TRUE mid layer 2_v5=TRUE mid layer 3_v5=TRUE mid layer 4_v5=TRUE bottom layer_v5=TRUE
RoutingVias RoutingVias_Laser_L1-2 [InDrillLayerPair('Top Layer - Signal Layer 1')] p1: holewidth=0.1 width=0.25 viastyle="Through Hole" minholewidth=0.1 minwidth=0.25 maxholewidth=0.1 maxwidth=0.25
RoutingVias RoutingVias_GND [InNetClass('NC_GND')] p2: holewidth=0.3 width=0.6 viastyle="Through Hole" minholewidth=0.2 minwidth=0.4 maxholewidth=0.3 maxwidth=0.6
RoutingVias RoutingVias_ALIMS [InNetClass('NC_ALIMS')] p3: holewidth=0.3 width=0.6 viastyle="Through Hole" minholewidth=0.2 minwidth=0.4 maxholewidth=0.3 maxwidth=0.6
RoutingVias [All] p4: holewidth=0.2 width=0.4 viastyle="Through Hole" minholewidth=0.2 minwidth=0.4 maxholewidth=0.2 maxwidth=0.4
SilkToSilkClearance [All] p1: silktosilkclearance=0
SilkToSolderMaskClearance [IsPad] p1: minsilkscreentomaskgap=0 clearancetoexposedcopper=TRUE
SolderMaskExpansion [All] p1: expansion=0.05
Width Width_BGA05 [InComponentClass('CC_BGA05')] p1: maxlimit=0.09 minlimit=0.09 preferedwidth=0.09
Width Width_GND [InNetClass('NC_GND')] p2: maxlimit=10 minlimit=0.09 preferedwidth=0.3
Width Width_ALIMS [InNetClass('NC_ALIMS')] p3: maxlimit=10 minlimit=0.09 preferedwidth=0.3
Width Width_SINGLE_55R_DDR [InNetClass('NC_SINGLE_55R_DDR')] p4: maxlimit=10 minlimit=0.09 preferedwidth=0.127 toplayer_prefwidth=0.12 midlayer1_prefwidth=0.12 midlayer3_prefwidth=0.12 midlayer4_prefwidth=0.12 bottomlayer_prefwidth=0.12 minimp=50.000000 maximp=50.000000 favimp=50.000000
Width Width_BUS_50R_SDMMC1_CK [InNetClass('NC_BUS_50R_SDMMC1_CK')] p5: maxlimit=0.13 minlimit=0.09 preferedwidth=0.13
Width Width_BUS_50R_SDMMC1 [InNetClass('NC_BUS_50R_SDMMC1')] p6: maxlimit=10 minlimit=0.09 preferedwidth=0.13
Width Width_ANTENNA_50R_WIFI [InNetClass('NC_ANTENNA_50R_WIFI')] p7: maxlimit=0.13 minlimit=0.13 preferedwidth=0.13
Width Width_BUS_50R_RGMII_ETH-TX [InNetClass('NC_BUS_50R_RGMII_ETH-TX')] p8: maxlimit=10 minlimit=0.09 preferedwidth=0.13
Width Width_BUS_50R_RGMII_ETH-RX [InNetClass('NC_BUS_50R_RGMII_ETH-RX')] p9: maxlimit=10 minlimit=0.09 preferedwidth=0.13
Width Width_BUS_50R_RGMII_ETH-CLK [InNetClass('NC_BUS_50R_RGMII_ETH-CLK')] p10: maxlimit=10 minlimit=0.09 preferedwidth=0.13
Width [All] p11: maxlimit=10 minlimit=0.09 preferedwidth=0.1
15 further rules are at their usual default settings.

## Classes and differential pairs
net class NC_SINGLE_55R_DDR: DDR_A0 DDR_A1 DDR_A2 DDR_A3 DDR_A4 DDR_A5 DDR_A6 DDR_A7 DDR_A8 DDR_A9 DDR_A10 DDR_A11 DDR_A12 DDR_A13 DDR_A14 DDR_BA0 DDR_BA1 DDR_BA2 DDR_CASN DDR_CKE DDR_CSN DDR_DQ0 DDR_DQ1 DDR_DQ2 DDR_DQ3 DDR_DQ4 DDR_DQ5 DDR_DQ6 DDR_DQ7 DDR_DQ8 DDR_DQ9 DDR_DQ10 DDR_DQ11 DDR_DQ12 DDR_DQ13 DDR_DQ14 DDR_DQ15 DDR_DQM0 DDR_DQM1 DDR_ODT DDR_RASN DDR_RESETN DDR_WEN
differential pair class DIFFPAIR_100R_DDR: DDR_CLK DDR_DQS0 DDR_DQS1
net class NC_DIFFPAIR_100R_DDR: DDR_CLK_N DDR_CLK_P DDR_DQS0_N DDR_DQS0_P DDR_DQS1_N DDR_DQS1_P
net class NC_ALIMS: 1V2_CVCC12 1V2_HDMI 1V05_AVDD_GMII 1V05_DVDD_GMII 1V05_GMII 1V8_AUDIO 3V3 3V3_AVDD_GMII 3V3_DVDD_GMII 3V3_HDMI 3V3_IOVCC 3V3_ST_LINK 5V 5V_USB_ST_LINK 5V_VIN NetC66_1 NetC66_2 NetR150_2 VDD VDD_CORE VDD_DDR VDD_USB VDDA VDDA_1V8 VREF+ VREF_DDR VTT_DDR
net class NC_GND: AGND GND
component class CC_BGA05: U13
differential pair class DIFFPAIR_100R_DSI: DSI_CK DSI_D0 DSI_D1
net class NC_DIFFPAIR_100R_DSI: DSI_CK_N DSI_CK_P DSI_D0_N DSI_D0_P DSI_D1_N DSI_D1_P
differential pair class DIFFPAIR_90R_USB: USB1 USB1CN25 USB2 USB2CN25 USB3CN26 USB4CN26 USB_DCONN USB_STLK USBDN1 USBDN2 USBDN3 USBDN4
net class NC_DIFFPAIR_90R_USB: USB1_N USB1_P USB1CN25_N USB1CN25_P USB2_N USB2_P USB2CN25_N USB2CN25_P USB3CN26_N USB3CN26_P USB4CN26_N USB4CN26_P USB_DCONN_N USB_DCONN_P USB_STLK_N USB_STLK_P USBDN1_N USBDN1_P USBDN2_N USBDN2_P USBDN3_N USBDN3_P USBDN4_N USBDN4_P
differential pair class DIFFPAIR_90R_USB_LENGTH: USB1CN25 USB2CN25 USB3CN26 USB4CN26 USBDN1 USBDN2 USBDN3 USBDN4
differential pair class DIFFPAIR_100R_HDMI-TX: TX0 TX0C TX1 TX1C TX2 TX2C TXC TXCC
net class NC_DIFFPAIR_100R_HDMI-TX: TX0_N TX0_P TX0C_N TX0C_P TX1_N TX1_P TX1C_N TX1C_P TX2_N TX2_P TX2C_N TX2C_P TXC_N TXC_P TXCC_N TXCC_P
net class NC_GROUP_LTDC: LTDC_B0 LTDC_B1 LTDC_B2 LTDC_B3 LTDC_B4 LTDC_B5 LTDC_B6 LTDC_B7 LTDC_CLK LTDC_DE LTDC_G0 LTDC_G1 LTDC_G2 LTDC_G3 LTDC_G4 LTDC_G5 LTDC_G6 LTDC_G7 LTDC_HSYNC LTDC_R0 LTDC_R1 LTDC_R2 LTDC_R3 LTDC_R4 LTDC_R5 LTDC_R6 LTDC_R7 LTDC_VSYNC
net class NC_GROUP_I2S2: I2S2_CK I2S2_SDO I2S2_WS
differential pair class DIFFPAIR_100R_HDMI-TX_LENGTH_1-2: TX0 TX1 TX2 TXC
differential pair class DIFFPAIR_100R_HDMI-TX_LENGTH_2-2: TX0C TX1C TX2C TXCC
net class NC_BUS_50R_SDMMC1: SDMMC1_D0 SDMMC1_D1 SDMMC1_D2 SDMMC1_D3
net class NC_BUS_50R_SDMMC1_CK: SDMMC1_CK
net class NC_BUS_50R_SDMMC1_ALL: SDMMC1_CK SDMMC1_D0 SDMMC1_D1 SDMMC1_D2 SDMMC1_D3
net class NC_BUS_50R_RGMII_ETH-TX: ETH_TXD0 ETH_TXD1 ETH_TXD2 ETH_TXD3
net class NC_BUS_50R_RGMII_ETH-RX: ETH_RXD0 ETH_RXD1 ETH_RXD2 ETH_RXD3
net class NC_BUS_50R_RGMII_ETH-CLK: ETH_CLK ETH_CLK125 ETH_GTX_CLK
net class NC_BUS_50R_RGMII_ETH-ALL: ETH_CLK ETH_CLK125 ETH_GTX_CLK ETH_RX_CLK ETH_RX_DV ETH_RXD0 ETH_RXD1 ETH_RXD2 ETH_RXD3 ETH_TX_EN ETH_TXD0 ETH_TXD1 ETH_TXD2 ETH_TXD3
net class NC_GROUP_I2C1: I2C1_SCL I2C1_SDA
net class NC_GROUP_I2C4: I2C4_SCL I2C4_SDA
net class NC_GROUP_USART2: USART2_CTS USART2_RTS USART2_RX USART2_TX
net class NC_GROUP_SAI2: SAI2_FSA SAI2_FSAM SAI2_MCLKA SAI2_SCKA SAI2_SCKAM SAI2_SDA SAI2_SDAM SAI2_SDB SAI2_SDBM
net class NC_GROUP_SDMMC2: SDMMC2_CK SDMMC2_CMD SDMMC2_D0 SDMMC2_D1 SDMMC2_D2 SDMMC2_D3
net class NC_GROUP_ETH-SIGNALS: ETH_MDC ETH_MDINT ETH_MDIO
differential pair class DIFFPAIR_100R_RGMII-RJ45: RJ45_D1 RJ45_D2 RJ45_D3 RJ45_D4
net class NC_DIFFPAIR_100R_RGMII-RJ45: RJ45_D1_N RJ45_D1_P RJ45_D2_N RJ45_D2_P RJ45_D3_N RJ45_D3_P RJ45_D4_N RJ45_D4_P
net class NC_ANTENNA_50R_WIFI: NetC8_2 NetC19_2 NetC34_2
differential pair CON_USB_STLK: +CON_USB_STLK_P -CON_USB_STLK_N
differential pair DDR_CLK: +DDR_CLK_P -DDR_CLK_N
differential pair USBDN4: +USBDN4_P -USBDN4_N
differential pair USBDN3: +USBDN3_P -USBDN3_N
differential pair USBDN2: +USBDN2_P -USBDN2_N
differential pair USBDN1: +USBDN1_P -USBDN1_N
differential pair USB_STLK: +USB_STLK_P -USB_STLK_N
differential pair USB_DCONN: +USB_DCONN_P -USB_DCONN_N
differential pair USB4CN26: +USB4CN26_P -USB4CN26_N
differential pair USB3CN26: +USB3CN26_P -USB3CN26_N
differential pair USB2CN25: +USB2CN25_P -USB2CN25_N
differential pair USB1CN25: +USB1CN25_P -USB1CN25_N
differential pair TXC: +TXC_P -TXC_N
differential pair TXCC: +TXCC_P -TXCC_N
differential pair TX2: +TX2_P -TX2_N
differential pair TX2C: +TX2C_P -TX2C_N
differential pair TX1: +TX1_P -TX1_N
differential pair TX1C: +TX1C_P -TX1C_N
differential pair TX0: +TX0_P -TX0_N
differential pair TX0C: +TX0C_P -TX0C_N
differential pair RJ45_D4: +RJ45_D4_P -RJ45_D4_N
differential pair RJ45_D3: +RJ45_D3_P -RJ45_D3_N
differential pair RJ45_D2: +RJ45_D2_P -RJ45_D2_N
differential pair RJ45_D1: +RJ45_D1_P -RJ45_D1_N
differential pair USB2: +USB2_P -USB2_N
differential pair USB1: +USB1_P -USB1_N
differential pair DSI_D1: +DSI_D1_P -DSI_D1_N
differential pair DSI_D0: +DSI_D0_P -DSI_D0_N
differential pair DSI_CK: +DSI_CK_P -DSI_CK_N
differential pair DDR_DQS1: +DDR_DQS1_P -DDR_DQS1_N
differential pair DDR_DQS0: +DDR_DQS0_P -DDR_DQS0_N

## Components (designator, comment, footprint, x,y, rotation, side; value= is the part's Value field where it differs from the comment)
B1 "" SWI_JIUBABA_C-TS-02H-2-5-B-V-T_R_BLUE 22,5.5 r180 top locked value=SW-PUSH-TS-02H-Blue
B2 "" SWI_JIUBABA_C-TS-02H-2-5-K-V-T_R_BLACK 43.8,5.5 r0 top locked value=SW-PUSH-TS-02H-Black
B3 "SW-PUSH-TS-02H-Blue" SWI_JIUBABA_C-TS-02H-2-5-B-V-T_R_BLUE 51.85,5.5 r180 top
B4 "SW-PUSH-TS-02H-Blue" SWI_JIUBABA_C-TS-02H-2-5-B-V-T_R_BLUE 59.9,5.5 r180 top locked
C1 "" C0402 64.825,59.725 r90 top value=100nF
C2 "" C0603 27.75,62.175 r0 top value=22uF
C3 "" C0603 34.9,62.15 r0 top value=22uF
C4 "" C0603 28.25,60.4 r270 top value=10uF
C5 "" C0603 32.25,60.95 r270 top value=10uF
C6 "" C0603 27.575,58.625 r0 top value=10uF
C7 "" C0402 24.85,58.3 r270 top value=100nF
C8 "Capacitor" C0402 3.425,57.725 r180 top value=12pF
C9 "" C0603 27.575,57.35 r0 top value=10uF
C10 "Capacitor" C0402 38.234,56.562 r0 top value=4.7uF
C11 "Capacitor" C0603 56.39,55.48 r270 top value=10uF
C12 "Capacitor" C0402 39.62,55.78 r90 top value=100nF
C13 "Capacitor" C0603 43.85,55.41 r90 top value=10uF
C14 "" C0402 44.92,55.71 r270 top value=100nF
C15 "" C0402 27.25,56.325 r0 top value=1uF
C16 "Capacitor" C0402 38.225,55.725 r180 top value=4.7uF
C17 "" C0402 55.3,55.29 r90 top value=100nF
C18 "Capacitor" C0402 60.25,54.74 r270 top value=100nF
C19 "Capacitor" C0402 3.425,54.9 r180 top value=12pF
C20 "Capacitor" C0402 27.25,55.4 r0 top value=4.7uF
C21 "Capacitor" C0402 66.45,54.025 r270 top value=100nF
C22 "" C0402 44.94,53.79 r270 top value=100nF
C23 "Capacitor" C0402 64.725,53.675 r0 top value=4.7uF
C24 "Capacitor" C0402 2.525,53.875 r0 top value=12pF
C25 "Capacitor" C0402 67.825,53.65 r180 top value=100nF
C26 "Capacitor" C0402 37.15,53.825 r180 top value=4.7uF
C27 "" C0402 27.25,54.325 r0 top value=1uF
C28 "Capacitor" C0603 7,52.525 r270 top value=2.2uF
C29 "Capacitor" C0603 8.45,52.525 r270 top value=10uF
C30 "Capacitor" C0402 69.625,53.175 r0 top value=100nF
C31 "Capacitor" C0402 27.25,51.9 r0 top value=4.7uF
C32 "Capacitor" C0402 27.25,53.175 r0 top value=4.7uF
C33 "Capacitor" C0402 29.35,51.6 r90 top value=4.7uF
C34 "Capacitor" C0402 2.525,51.325 r0 top value=12pF
C35 "" C0402 55.14,50.84 r90 top value=100nF
C36 "" C0402 44.91,50.58 r90 top value=100nF
C37 "Capacitor" C0402 9.575,50.425 r270 top value=4.7uF
C38 "Capacitor" C0402 62.5,50.075 r270 top value=100nF
C39 "" C0402 27.25,51.075 r0 top value=1uF
C40 "Capacitor" C0402 72.55,49.6 r270 top value=100nF
C41 "" C0603 29.75,49.55 r90 top value=10uF
C42 "" C0603 30.55,47.45 r0 top value=22uF
C43 "" C0603 33.625,49.55 r90 top value=10uF
C44 "" C0603 34.45,47.45 r0 top value=22uF
C45 "" C0402 10.45,48.6 r180 top value=100nF
C46 "" C0402 55.23,47.15 r90 top value=100nF
C47 "" C0402 44.92,46.08 r90 top value=100nF
C48 "" C0402 55.23,45.41 r270 top value=100nF
C49 "Capacitor" C0402 15.6,45.775 r180 top value=4.7uF
C50 "Capacitor" C0402 64.375,45.125 r0 top value=100nF
C51 "" C0402 26.1,44.55 r90 top value=100nF
C52 "" CPOL_TAJ-A_1206_H180 28.65,44.2 r0 top value=10uF
C53 "Capacitor" C0402 68.65,44.525 r90 top value=100nF
C54 "Capacitor" C0402 70.6,44.525 r90 top value=100nF
C55 "Capacitor" C0805 73.05,43.5 r90 top value=47uF
C56 "Capacitor" C0402 74.4,43.9 r90 top value=100nF
C57 "" C0402 55.23,43.67 r270 top value=100nF
C58 "Capacitor" C0402 65.2,41.5 r270 top value=6.8pF
C59 "Capacitor" C0402 68.75,41.45 r90 top value=6.8pF
C60 "Cap_POL_TANA" CPOL_TAJ-C_2312_H2P6 15.05,39.9 r180 top value=47uF
C61 "" C0402 10.5,39.425 r180 top value=100nF
C62 "Capacitor" C0402 79.8,38.05 r180 top value=1uF
C63 "Capacitor" C0402 39.88,37.43 r270 top value=100nF
C64 "" C0402 41.79,37.165 r270 top value=1uF
C65 "Capacitor" C0402 79.8,36.45 r180 top value=1uF
C66 "Capacitor" C0402 82.075,36.4 r0 top value=100nF
C67 "Capacitor" C0402 60.36,35.18 r270 top value=100nF
C68 "" C0402 57.55,35.32 r180 top value=100nF
C69 "Capacitor" C0402 11.925,33.3 r270 top value=100pF
C70 "" C0402 12.825,33.3 r90 top value=100nF
C71 "Capacitor" C0805 17.2,32.8 r180 top value=10uF
C72 "" C0402 58.705,32.04 r180 top value=1uF
C73 "" C0402 60.005,31.59 r270 top value=1uF
C74 "" C0402 25.6,30.35 r0 top value=100nF
C75 "" C0402 25.6,29.45 r0 top value=100nF
C76 "" C0603 27.125,28.375 r90 top value=22uF
C77 "" C0402 25.6,28.55 r0 top value=100nF
C78 "" C0402 25.6,27.65 r0 top value=100nF
C79 "" C0402 27.3,26.75 r180 top value=100nF
C80 "" C0603 25.275,26.525 r0 top value=22uF
C81 "" C0402 33.85,26.675 r180 top value=100nF
C82 "" C0402 19.825,26.2 r270 top value=10pF
C83 "Capacitor" C0402 84.35,25.625 r90 top value=470pF
C84 "Capacitor" C0402 89.05,25.625 r90 top value=470pF
C85 "" C0603 33.625,25.55 r180 top value=22uF
C86 "" C0402 19.825,24.4 r90 top value=10pF
C87 "Capacitor" C0402 55.175,20.225 r90 top value=6.8pF
C88 "Capacitor" C0402 53.525,21.625 r180 top value=6.8pF
C89 "" C0402 56.55,20.25 r90 top value=1uF
C90 "Capacitor" C0402 46.925,20.125 r270 top value=6.8pF
C91 "Capacitor" C0402 50.625,20.175 r270 top value=6.8pF
C92 "Capacitor" C0402 45.075,19.15 r90 top value=10nF
C93 "" C0402 64.9,17.775 r90 top value=100nF
C94 "" C0402 45.975,17.55 r270 top value=1uF
C95 "" C0402 46.875,17.55 r270 top value=100nF
C96 "" C0402 47.8,17.55 r90 top value=100nF
C97 "" C0402 45.075,16.775 r270 top value=100nF
C98 "" C0402 61.625,16.025 r90 top value=10pF
C99 "" C0402 61.625,13.925 r270 top value=10pF
C100 "" C0603 48.95,14.05 r180 top value=150pF
C101 "" C0603 48.95,12.7 r180 top value=150pF
C102 "" C0402 39.975,12.1 r0 top value=1uF
C103 "" C0402 48.625,11.575 r180 top value=100nF
C104 "" C0603 40.15,9.85 r90 top value=1uF
C105 "" C0402 48.625,9.625 r180 top value=1uF
C106 "" C0402 27.45,9.2 r270 top value=22nF
C107 "" C0402 44.175,8.875 r90 top value=100nF
C108 "" C0402 45.4,8.875 r90 top value=1uF
C109 "" C0402 46.3,8.875 r90 top value=1uF
C110 "" C0603 41.55,8.525 r90 top value=1uF
C111 "" C0603 49.025,8.5 r180 top value=10uF
C112 "" C0402 90.4,5.95 r90 top value=1uF
C113 "" C0402 27.45,5.8 r270 top value=22nF
C114 "" C0402 25.25,5.5 r90 top value=10nF
C115 "Capacitor" C0402 39.5,4.425 r90 top value=10nF
C117 "Capacitor" C0402 83.95,59.575 r0 bottom value=100nF
C118 "Capacitor" C1206_H1P6 82.55,58.025 r0 bottom value=220uF
C119 "" C0402 58.125,57.75 r0 bottom value=100nF
C120 "" C0402 42.375,57.75 r180 bottom value=100nF
C121 "" C0603 58.41,56.26 r180 bottom value=22uF
C122 "" C0603 41.975,56.2 r0 bottom value=22uF
C123 "Capacitor" C0402 83.95,56.475 r0 bottom value=100nF
C124 "Capacitor" C1206_H1P6 82.55,54.925 r0 bottom value=220uF
C125 "" C0402 58.02,53.83 r0 bottom value=100nF
C126 "" C0402 42.36,53.72 r180 bottom value=100nF
C127 "" C0402 58.02,51.74 r0 bottom value=100nF
C128 "" C0402 42.36,51.51 r180 bottom value=100nF
C129 "" C0402 58.02,49.59 r0 bottom value=100nF
C130 "" C0402 42.36,49.3 r180 bottom value=100nF
C131 "" C0402 42.36,47.2 r180 bottom value=100nF
C132 "" C0402 58.02,47.01 r0 bottom value=100nF
C133 "Capacitor" C1206_H1P6 82.55,44.65 r0 bottom value=220uF
C134 "" C0402 42.36,45.08 r180 bottom value=100nF
C135 "" C0402 58.02,44.24 r0 bottom value=100nF
C136 "Capacitor" C0402 83.95,43.1 r0 bottom value=100nF
C137 "Capacitor" C0402 83.95,42.2 r0 bottom value=100nF
C138 "Capacitor" C1206_H1P6 82.55,40.65 r0 bottom value=220uF
C139 "" C0402 54.255,32.94 r90 bottom value=100nF
C140 "" C0402 75.7,32.475 r270 bottom value=100nF
C141 "" C0402 73.925,32.025 r270 bottom value=100nF
C142 "" C0402 70.425,32.025 r270 bottom value=100nF
C143 "" C0402 52.49,32.33 r0 bottom value=1uF
C144 "" C0402 50.87,32.33 r0 bottom value=1nF
C145 "" C0402 49.25,32.31 r0 bottom value=1nF
C146 "" C0402 47.62,32.31 r0 bottom value=1uF
C147 "" C0402 53.35,31.275 r180 bottom value=1uF
C148 "" C0402 48.13,31.015 r315 bottom value=1uF
C149 "" C0402 45.65,31.275 r45 bottom value=100nF
C150 "" C0402 50.243,30.852 r135 bottom value=1uF
C151 "" C0603 22.725,30.375 r180 bottom value=22uF
C152 "" C0402 53.35,30.175 r180 bottom value=1uF
C153 "" C0402 46.8,29.525 r0 bottom value=1uF
C154 "" C0402 66.875,30.475 r0 bottom value=100nF
C155 "" C0402 48.943,29.552 r135 bottom value=1uF
C156 "" C0402 46.8,28.7 r0 bottom value=1uF
C157 "" C0402 22.475,29.25 r180 bottom value=100nF
C158 "" C0402 53.35,29.45 r180 bottom value=1uF
C159 "" C0402 50.568,28.577 r135 bottom value=1uF
C160 "" C0402 76.475,28.475 r180 bottom value=100nF
C161 "" C0402 53.35,28.725 r180 bottom value=1uF
C162 "" C0402 49.6,27.7 r135 bottom value=1uF
C163 "" C0402 48.13,27.603 r135 bottom value=1uF
C164 "" C0402 66.875,27.975 r0 bottom value=100nF
C165 "" C0402 51.75,27.35 r270 bottom value=1uF
C166 "Capacitor" C0805 97.625,25.875 r270 bottom value=10uF
C167 "Capacitor" C0402 96.275,25.475 r270 bottom value=100pF
C168 "" C0402 76.475,25.475 r180 bottom value=100nF
C169 "" C0402 75.425,22.425 r90 bottom value=100nF
C170 "" C0402 72.825,22.425 r90 bottom value=100nF
C171 "" C0402 71.925,22.425 r90 bottom value=100nF
C172 "" C0402 69.925,22.425 r90 bottom value=100nF
C173 "" C0603 27.9,20.85 r270 bottom value=22uF
C174 "" C0402 30.825,20.525 r270 bottom value=100nF
C175 "" C0402 29.925,20.525 r270 bottom value=100nF
C176 "" C0402 29.025,20.525 r270 bottom value=100nF
C177 "" C0402 31.225,18.075 r90 bottom value=100nF
C178 "" C0402 30.325,18.075 r90 bottom value=100nF
C179 "" C0402 29.425,18.075 r90 bottom value=100nF
C180 "" C0603 28.3,17.75 r90 bottom value=22uF
C181 "" C0402 74.75,17.225 r180 bottom value=100nF
C182 "" C0402 66.25,14.225 r0 bottom value=100nF
C183 "" C0402 11.95,13.875 r0 bottom value=100nF
C184 "" C0402 66.25,13.225 r0 bottom value=100nF
C185 "" C0603 82.35,11.85 r180 bottom value=1uF
C186 "" C0402 73.25,10.225 r270 bottom value=100nF
C187 "" C0402 79.425,10.225 r90 bottom value=100nF
C188 "" C0402 79.425,8.025 r270 bottom value=100nF
C189 "" C0402 82.675,6.625 r180 bottom value=10nF
C190 "" C0603 80.15,6.4 r0 bottom value=1uF
C191 "" C0402 53.45,27.65 r180 bottom value=1uF (schematic designator C1600)
C192 "" C0402 46.23,30.69 r45 bottom value=1uF (schematic designator C1620)
C300 "Capacitor" C0402 51.6,18.325 r0 top value=10nF
CN1 "USB_DUAL_TYPEA_5600-3081" CON_DUAL-USB-TYPE-A_CONEXCON_5600-3081 103,62 r90 top locked value="Dual USB Type A"
CN2 "" CON_SAMTEC_TSW-120-07-G-D 51.5,67.5 r0 top locked value="Header 20x2"
CN3 "" CON_MOLEX_53047-0210 22.9,58.325 r90 top locked value=53047-0210
CN4 "" CON_TE-CONNECTIVITY_2-1734248-0 22.5,41.5 r270 top locked value=2-1734248-0
CN5 "USB_DUAL_TYPEA_5600-3081" CON_DUAL-USB-TYPE-A_CONEXCON_5600-3081 103,44 r90 top locked value="Dual USB Type A"
CN6 "" CON_USB-TYPEC_COXOC_317JD24BZTF3K3C3 -1,31.5 r270 top locked value=317JD24BZTF3K3C3
CN7 "" CON_USB-TYPEC_COXOC_317JD24BZTF3K3C3 102,27.775 r90 top locked value=317JD24BZTF3K3C3
CN8 "​New part for use of led pulled down on pin 13/14 , schematic more lisible." CON_RJ45_YD_48F-01GYDXNL_LED-P 0,14.5 r270 top locked value=48F-01GYDXNL
CN9 "" CON_HDMI_FCI-AMPHENOL_10029449-001RLF 102,9.5 r90 top locked value=10029449-001RLF
CN10 "" CON_JACK-3P5-SMT_LUMBERG_1503-13-VP3 33.5,-2.6 r90 top locked value="1503 13 VP3"
CN11 "" CON_USBMICROB_MOLEX_105017-0001_H2P90 75.5,0 r0 top locked value=USB_uB_105017-0001
CN12 "" CON_SAMTEC_TSW-104-07-G-S 85.5,1.525 r0 top locked value="Header 4x1"
CN13 "" CON_SAMTEC_SSW-110-22-X-S-VS 59.434,61.45 r180 bottom locked value="Socket 10x1"
CN14 "" CON_SAMTEC_SSW-108-22-X-S-VS 35.05,61.45 r180 bottom locked value="Socket 8x1"
CN15 "" CON_MICROSD_YAMAICHI_PJS008-2003-0 0,45 r180 bottom locked value=PJS008-2003-1
CN16 "" CON_SAMTEC_SSW-108-22-X-S-VS 52.83,13.19 r0 bottom locked value="Socket 8x1"
CN17 "" CON_SAMTEC_SSW-106-22-X-S-VS 32.51,13.19 r0 bottom locked value="Socket 6x1"
D1 "" DIO_SOD323 84.575,11.075 r90 bottom value=BAT60JFILM
D2 "" DIO_SOD323 76.425,11.875 r0 bottom value=BAT60JFILM
F1 "​f" R0805 88.35,5.925 r0 top value=picoSMDC035S
H1 "" PTH_M1261-3005-N_3P5X6_M3_H14 22.5,67.5 r0 top locked
H2 "" PTH_M1261-3005-N_3P5X6_M3_H14 80.5,67.5 r0 top locked
H3 "" PTH_M1261-3005-N_3P5X6_M3_H14 22.5,18.5 r0 top locked
H4 "" PTH_M1261-3005-N_3P5X6_M3_H14 80.5,18.5 r0 top locked
L1 "Inductor" IND_0402_MURATA_LQW15AN2N4C00X 2.975,62.25 r90 top value=LQW15AN2N4C00x
L2 "IND_1uH_42mohm_3.2A" IND_2520_TOKO_DFE252012P 30.275,60.9 r90 top value=1µH
L3 "IND_1uH_42mohm_3.2A" IND_2520_TOKO_DFE252012P 34.675,60.225 r0 top value=1µH
L4 "Inductor" L0603 8.375,49.825 r270 top value=LQM18PN2R2MGH
L5 "IND_1uH_42mohm_3.2A" IND_2520_TOKO_DFE252012P 31.675,49.625 r270 top value=1µH
L6 "IND_1uH_42mohm_3.2A" IND_2520_TOKO_DFE252012P 35.575,49.625 r270 top value=1µH
L7 "BEAD" L0603 27.1,46.15 r180 top value=30R@100MHz
L8 "BEAD" FIL_0603_H0P65 76.3,44.35 r0 top value=26ohm
L9 "LQM18FN4R7M00D" L0603 58.65,21.85 r180 top
L10 "" FIL_0603_H0P65 32.375,18.725 r0 top value=100R@100MHz
L11 "" FIL_0603_H0P65 26.3,29.4 r0 bottom value=100R@100MHz
LD1 "LED_red" LED_0603_RED 61.125,45.05 r270 top value=RED
LD2 "" LED_0603_GREEN 8.2,37.225 r180 top value=GREEN
LD3 "" LED_0603_GREEN 11.525,25.3 r180 top value=GREEN
LD4 "" LED_BI-GR_HSMF-A201-A00J1 81.625,8.65 r0 top value=LD_BICOLOR_CMS
LD5 "" LED_0603_GREEN 47.3,5.025 r270 top value=GREEN
LD6 "" LED_0603_RED 55.35,5.025 r270 top value=RED
LD7 "LED_orange" LED_0603_ORANGE_H0P4 63.825,5.025 r270 top value=ORANGE
LD8 "​reference from jiubaba" LED_0603_SMD-B_BLUE_H0P4 68,4.85 r270 top value=BLUE
LD9 "" LED_0603_GREEN 69.475,56.475 r180 bottom value=GREEN
LE1 "" L1210_LQH 21.975,27 r180 bottom value="4.7uH 1A 180R"
LNK1 "link_200" LINK200#1 38.575,33.3 r180 top
LNK2 "link_200" LINK200#2 46.512,29.3 r270 top
MIRE-PLACE-1 "MIRE-PLACE-1" MIRE_PLACE_SMD_0P8MM 18.325,62.575 r0 top
MIRE-PLACE-2 "MIRE-PLACE-2" MIRE_PLACE_SMD_0P8MM 97.075,53.025 r0 top
MIRE-PLACE-3 "MIRE-PLACE-3" MIRE_PLACE_SMD_0P8MM 4.575,1.85 r0 top
MIRE-PLACE-4 "MIRE-PLACE-4" MIRE_PLACE_SMD_0P8MM 99.05,68.225 r180 bottom
MIRE-PLACE-5 "MIRE-PLACE-5" MIRE_PLACE_SMD_0P8MM 18.15,60.4 r180 bottom
MIRE-PLACE-6 "MIRE-PLACE-6" MIRE_PLACE_SMD_0P8MM 2.05,1.875 r180 bottom
Q1 "" DIO_SOT363 13.1,36.575 r90 top value=BCM857BS7F
Q2 "" MOS_POWERFLAT_3P3X3P3_P065 16.65,35.825 r180 top value=STL9P3LLH6
R1 "" R0402 58.95,61.45 r270 top value=1K5
R2 "" R0402 59.875,61.45 r270 top value=1K5
R3 "" R0603 37.225,62.175 r0 top value=0R_0603_ULO
R4 "" R0402 65.784,59.736 r90 top value=0R
R5 "" R0402 39.025,59.35 r90 top value=1K5
R6 "" R0402 40.15,58 r180 top value=0R
R7 "" R0402 40.074,59.363 r90 top value=1K5
R8 "Resistor" R0402 2.975,56.325 r270 top value=0R
R9 "" R0402 37.175,54.675 r180 top value=0R
R10 "Resistor" R0402 2.975,52.6 r270 top value=0R
R11 "" R0402 19.625,52.775 r270 top value=10K
R12 "Resistor" R0402 39.625,52.3 r90 top value=47K
R13 "" R0402 15.6,52.225 r180 top value=0R
R14 "" R0402 15.6,50.175 r180 top value=47K
R15 "" R0402 55.155,48.84 r90 top value=240R
R16 "" R0402 15.6,49.075 r180 top value=47K
R17 "Resistor" R0402 10.45,47.5 r180 top value=47K
R18 "Resistor" R0402 62.575,47.15 r180 top value=10K
R19 "" R0402 15.6,46.875 r180 top value=10K
R20 "Resistor" R0402 10.45,46.3 r180 top value=47K
R21 "Resistor" R0402 62.575,46.1 r0 top value=1K
R22 "Resistor" R0402 10.45,45.1 r180 top value=47K
R23 "Resistor" R0402 62.575,45.05 r0 top value=100K
R24 "Resistor" R0402 69.625,44.525 r90 top value=12K
R25 "" R0402 15.6,44.675 r180 top value=47K
R26 "Resistor" R0402 8.375,43.9 r180 top value=47K
R27 "Resistor" R0402 10.45,43.9 r180 top value=47K
R28 "" R0402 15.6,43.575 r180 top value=47K
R31 "Resistor" R0402 75.525,42.175 r270 top value=0R
R32 "Resistor" R0402 76.575,42.175 r90 top value=0R
R33 "" R0402 15.6,42.475 r180 top value=47K
R34 "Resistor" R0402 79.5,40.375 r180 top value=0R
R35 "Resistor" R0402 75.3,40.325 r0 top value=0R
R36 "Resistor" R0402 73.425,39.65 r270 top value=0R
R37 "Resistor" R0402 44.74,39.76 r180 top value=10K
R38 "" R0402 47.5,39.17 r180 top value=240R
R39 "Resistor" R0402 10.5,38.45 r0 top value=47K
R40 "Resistor" R0402 61.5,37.325 r270 top value=10K
R41 "" R0402 10.5,37.225 r0 top value=330R
R42 "Resistor" R0402 82.075,35.425 r0 top value=10K
R43 "Resistor" R0402 79.8,35.425 r180 top value=1K
R44 "" R0402 59.025,34.7 r270 top value=3K
R45 "Resistor" R0402 12.325,34.675 r180 top value=47K
R46 "Resistor" R0402 74.625,34.275 r0 top value=0R
R47 "" R0603 14.475,33 r0 top value=0R_0603_ULO
R48 "Resistor" R0402 17.725,31.05 r270 top value=5K1
R49 "Resistor" R0402 19.1,30.6 r0 top value=47K
R50 "" R0402 28.875,29.95 r270 top value=4K7
R51 "" R0402 30.575,29.95 r270 top value=4K7
R52 "" R0402 32.275,29.95 r90 top value=4K7
R53 "" R0402 33.975,29.95 r90 top value=4K7
R54 "" R0402 35.675,29.95 r270 top value=4K7
R55 "" R0402 37.4,29.95 r90 top value=4K7
R56 "Resistor" R0402 19.1,29.3 r0 top value=47K
R57 "Resistor" R0402 17.725,28.85 r90 top value=5K1
R58 "" R0402 28.875,28.25 r270 top value=0R
R59 "" R0402 30.575,28.25 r270 top value=0R
R60 "" R0402 32.275,28.25 r270 top value=22R
R61 "" R0402 33.975,28.225 r270 top value=22R
R62 "" R0402 35.675,28.225 r270 top value=22R
R63 "" R0402 37.4,28.225 r270 top value=22R
R64 "" R0402 21.125,25.875 r0 top value=0R
R65 "" R0402 25.4,25.3 r180 top value=1K5
R66 "" R0402 9.525,24.85 r90 top value=510R
R67 "" R0402 13.5,24.85 r90 top value=4K7
R68 "" R0402 21.125,24.725 r0 top value=0R
R69 "" R0402 23.375,23.675 r0 top value=22R
R70 "" R0402 77.8,22.575 r270 top value=5K1
R71 "" R0402 49.575,22.3 r270 top value=0R
R72 "" R0402 64.5,22.3 r0 top value=0R
R73 "" R0402 52.075,20.075 r90 top value=0R
R74 "" R0402 56.35,22.075 r180 top value=0R
R75 "" R0402 33.525,21.2 r270 top value=1K5
R76 "" R0402 34.6,21.2 r270 top value=1K5
R77 "" R0402 64.5,21.25 r180 top value=0R
R78 "" R0402 57.525,20.25 r90 top value=0R
R79 "" R0402 59.575,20.25 r90 top value=0R
R80 "" R0402 64.5,20.2 r0 top value=10K
R81 "" R0402 64.5,19.15 r180 top value=10K
R82 "Resistor" R0402 50.975,17.125 r0 top value=1K
R83 "" R0603 50.825,14.75 r90 top value=0R
R84 "" R0402 48.625,15.25 r180 top value=10K
R85 "" R0402 39.65,14.625 r90 top value=0R
R86 "" R0402 40.7,14.625 r90 top value=0R
R87 "" R0402 39.975,13.075 r180 top value=10K
R88 "" R0402 76.15,12.55 r270 top value=100R
R89 "" R0402 80.875,12.05 r90 top value=330R
R90 "" R0402 82.375,12.05 r90 top value=330R
R91 "" R0402 64.5,11.975 r0 top value=4K7
R92 "" R0402 27.45,10.9 r270 top value=51R
R93 "" R0402 76.15,10.85 r270 top value=1K5
R94 "" R0402 64.5,10.925 r0 top value=4K7
R95 "" R0402 48.625,10.6 r180 top value=2K2
R96 "" R0402 50,10.025 r270 top value=10K
R97 "" R0402 83.925,9.825 r270 top value=2K2
R98 "" R0402 84.975,9.825 r270 top value=2K2
R99 "" R0402 73.125,8.775 r180 top value=10K
R100 "" R0402 77.525,8.775 r180 top value=100K
R101 "" R0402 57.95,7.975 r0 top value=1K
R102 "" R0402 59.75,7.975 r180 top value=1K
R103 "" R0402 27.45,7.5 r270 top value=51R
R104 "" R0402 70.525,7.3 r90 top value=100R
R105 "" R0402 47.3,7.225 r90 top value=330R
R106 "" R0402 55.35,7.225 r90 top value=1K
R107 "Resistor" R0402 63.825,7.225 r270 top value=680R
R108 "Resistor" R0402 68,7.225 r270 top value=680R
R109 "" R0402 40.35,7.175 r90 top value=10K
R110 "" R0402 48.425,6.525 r90 top value=100R
R111 "" R0402 56.475,6.525 r90 top value=100R
R112 "" R0402 70.525,5.5 r90 top value=36K
R114 "" R0402 71.35,56.925 r90 bottom value=510R
R115 "" R0402 50.06,56.86 r90 bottom value=56R
R116 "" R0402 48.97,56.86 r90 bottom value=56R
R117 "" R0402 47.9,56.86 r90 bottom value=56R
R118 "" R0402 46.82,56.86 r90 bottom value=56R
R119 "" R0402 63.65,56.75 r270 bottom value=100K
R120 "" R0402 62.275,56.3 r0 bottom value=47K
R121 "" R0402 56.31,54.26 r0 bottom value=56R
R122 "" R0402 44.23,54.22 r180 bottom value=56R
R123 "" R0402 56.31,53.19 r0 bottom value=56R
R124 "" R0402 44.23,53.15 r180 bottom value=56R
R125 "Resistor" R0402 51.69,52.36 r180 bottom value=100R
R126 "" R0402 56.31,52.13 r0 bottom value=56R
R127 "Resistor" R0402 63.825,51.8 r90 bottom value=100K
R128 "" R0402 44.23,52.06 r180 bottom value=56R
R129 "Resistor" R0402 62,51.35 r0 bottom value=100K
R130 "" R0402 56.31,51.06 r0 bottom value=56R
R131 "" R0402 44.23,50.96 r180 bottom value=56R
R132 "" R0402 56.31,49.99 r0 bottom value=56R
R133 "" R0402 44.23,49.88 r180 bottom value=56R
R134 "Resistor" R0402 63.825,49.175 r90 bottom value=100K
R135 "" R0402 56.31,48.91 r0 bottom value=56R
R136 "Resistor" R0402 55.01,48.54 r90 bottom value=10K
R137 "Resistor" R0402 62,48.8 r0 bottom value=100K
R138 "" R0402 44.23,48.79 r180 bottom value=56R
R139 "Resistor" R0402 64.175,47.75 r180 bottom value=100K
R140 "Resistor" R0402 62,47.75 r180 bottom value=100K
R141 "" R0402 44.23,47.71 r180 bottom value=56R
R142 "" R0402 56.31,47.54 r0 bottom value=56R
R143 "" R0402 44.23,46.65 r180 bottom value=56R
R144 "" R0402 56.31,46.44 r0 bottom value=56R
R145 "" R0402 44.23,45.57 r180 bottom value=56R
R146 "" R0402 56.31,45.35 r0 bottom value=56R
R147 "" R0402 44.23,44.49 r180 bottom value=56R
R148 "" R0402 56.31,44.27 r0 bottom value=56R
R149 "" R0402 76.65,30.725 r90 bottom value=4K7
R150 "Resistor" R0603 99.225,25.725 r90 bottom value=0R_0603_ULO
R151 "" R0603 29.975,26.225 r180 bottom value=0R
R152 "" R0402 74.6,24.15 r90 bottom value=0R
R153 "" R0402 26.7,23.4 r270 bottom value=22R
R154 "" R0402 68.425,22.425 r270 bottom value=0R
R155 "" R0402 26.7,21.625 r90 bottom value=2K49
R156 "" R0402 4.95,21.575 r270 bottom value=4K7
R157 "" R0402 1.8,21.575 r90 bottom value=510R
R158 "" R0402 73,18.725 r0 bottom value=0R
R159 "" R0402 69.25,18.725 r0 bottom value=100K
R160 "" R0603 26.925,17.75 r90 bottom value=0R
R161 "" R0402 68.45,13.775 r270 bottom value=100K
R162 "" R0402 4.95,10.875 r270 bottom value=510R
R163 "" R0402 1.8,10.875 r270 bottom value=4K7
R164 "Resistor" R0402 88.125,6.85 r0 bottom value=10K
R165 "" R0402 51.55,9.125 r90 bottom value=0R
R166 "" R0402 37.65,8 r90 bottom value=1K5
R167 "" R0402 32.65,8 r90 bottom value=1K5
R300 "Resistor" R0402 33.125,19.875 r180 top value=10K
R302 "Resistor" R0402 53.1,17.875 r270 top value=10K
R303 "" R0402 51.8,21.475 r180 top value=1K
R304 "Resistor" R0402 58.75,18 r180 top value=10R
R600 "Resistor" R0402 60.006,47.3 r270 top value=10K
SB1 "" SOLDER-BRIDGE_R0603-0R 39.725,18.1 r90 top
SB2 "" SOLDER-BRIDGE_R0603-0R 41.125,18.1 r90 top
SB3 "" SOLDER-BRIDGE_R0603-0R 42.525,18.1 r90 top
SB4 "" SOLDER-BRIDGE_R0603-0R 43.925,18.1 r90 top
SB5 "" SOLDER-BRIDGE_R0603-0R 48.95,18.1 r270 top
SB6 "" SOLDER-BRIDGE_R0603-0R 61.225,57.525 r0 bottom
SB7 "SB_OFF" SOLDER-BRIDGE_R0603-0R 65.85,51.35 r180 bottom
SB8 "SB_OFF" SOLDER-BRIDGE_R0603-0R 65.85,49.6 r180 bottom
SB9 "" SOLDER-BRIDGE_R0603-0R 62.175,21.85 r90 bottom
SB10 "" SOLDER-BRIDGE_R0603-0R 60.775,21.85 r90 bottom
SB11 "" SOLDER-BRIDGE_R0603-0R 60.775,18.95 r90 bottom
SB12 "" SOLDER-BRIDGE_R0603-0R 62.175,18.95 r90 bottom
SB13 "" SOLDER-BRIDGE_R0603-0R 43.925,18.1 r90 bottom
SB14 "" SOLDER-BRIDGE_R0603-0R 42.525,18.1 r90 bottom
SB15 "" SOLDER-BRIDGE_R0603-0R 41.125,18.1 r90 bottom
SB16 "" SOLDER-BRIDGE_R0603-0R 39.725,18.1 r90 bottom
SB17 "" SOLDER-BRIDGE_R0603-0R 66.8,16.875 r180 bottom
SB18 "" SOLDER-BRIDGE_R0603-0R 66.8,15.375 r0 bottom
SB19 "" SOLDER-BRIDGE_R0603-0R 72,13.525 r180 bottom
SB20 "" SOLDER-BRIDGE_R0603-0R 66.8,11.975 r180 bottom
SB21 "" SOLDER-BRIDGE_R0603-0R 79.675,11.875 r0 bottom
SB22 "" SOLDER-BRIDGE_R0603-0R 66.8,10.125 r180 bottom
SB23 "SB_ON" SOLDER-BRIDGE_R0603-0R 36.425,8.55 r270 bottom
SB24 "" SOLDER-BRIDGE_R0603-0R 35.025,8.55 r270 bottom
SB25 "SB_ON" SOLDER-BRIDGE_R0603-0R 31.425,8.55 r270 bottom
SB26 "" SOLDER-BRIDGE_R0603-0R 30.025,8.55 r270 bottom
SW1 "SWITCH_2WAY" SWI_C&K_SDA02H1SBD_2POS 96.475,9.725 r0 bottom
T1 "" MOS_POWERFLAT_3P3X3P3_P065 82.85,32.375 r180 top value=STL9P3LLH6
T2 "" MOS_POWERFLAT_3P3X3P3_P065 87.35,32.375 r180 top value=STL9P3LLH6
T3 "" NPN_SOT23 70.525,6.275 r0 bottom value=SOT23
T4 "" NPN_SOT23 66.125,56.475 r90 bottom value=SOT23
TP1 "Test Point" TP_SMD_1MM 64.3,61.4 r90 top
TP2 "Test Point" TP_SMD_1MM 40.592,46.652 r180 top
TP3 "Test Point" TP_SMD_1MM 40.605,44.965 r180 top
TP4 "Test Point" TP_SMD_1MM 38.905,43.265 r180 top
TP5 "Test Point" TP_SMD_1MM 40.605,43.265 r180 top
TP6 "Test Point" TP_SMD_1MM 2.475,42.05 r90 top
TP7 "Test Point" TP_SMD_1MM 4.375,42.05 r90 top
TP8 "Test Point" TP_SMD_1MM 38.905,41.54 r180 top
TP9 "Test Point" TP_SMD_1MM 40.605,41.54 r180 top
TP10 "" TP_SMD_0-6MM 41.79,40.81 r180 top
TP11 "Test Point" TP_SMD_1MM 2.475,40.15 r90 top
TP12 "Test Point" TP_SMD_1MM 4.375,40.15 r90 top
TP13 "" TP_SMD_0-6MM 41.79,38.89 r180 top
TP14 "" TP_SMD_0-6MM 58.43,37.48 r90 top
TP15 "Test Point" TP_SMD_1MM 72.43,36.865 r90 top
TP16 "Test Point" TP_SMD_1MM 73.05,35.375 r90 top
TP17 "Test Point" TP_SMD_1MM 76.475,33.675 r90 top
TP18 "Test Point" TP_SMD_1MM 78.125,32.7 r90 top
TP19 "Test Point" TP_SMD_1MM 41.23,30.89 r90 top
